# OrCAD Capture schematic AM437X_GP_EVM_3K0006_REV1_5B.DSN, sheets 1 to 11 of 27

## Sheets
1 Pg26: USB JTAG: size C; title: AM4378 General Purpose EVM; rev: 1.5B; company: Texas Instruments; note: am437x_gp_evm_3k0006_rev1_5b.dsn; note: ARM MPU BU; note: Final
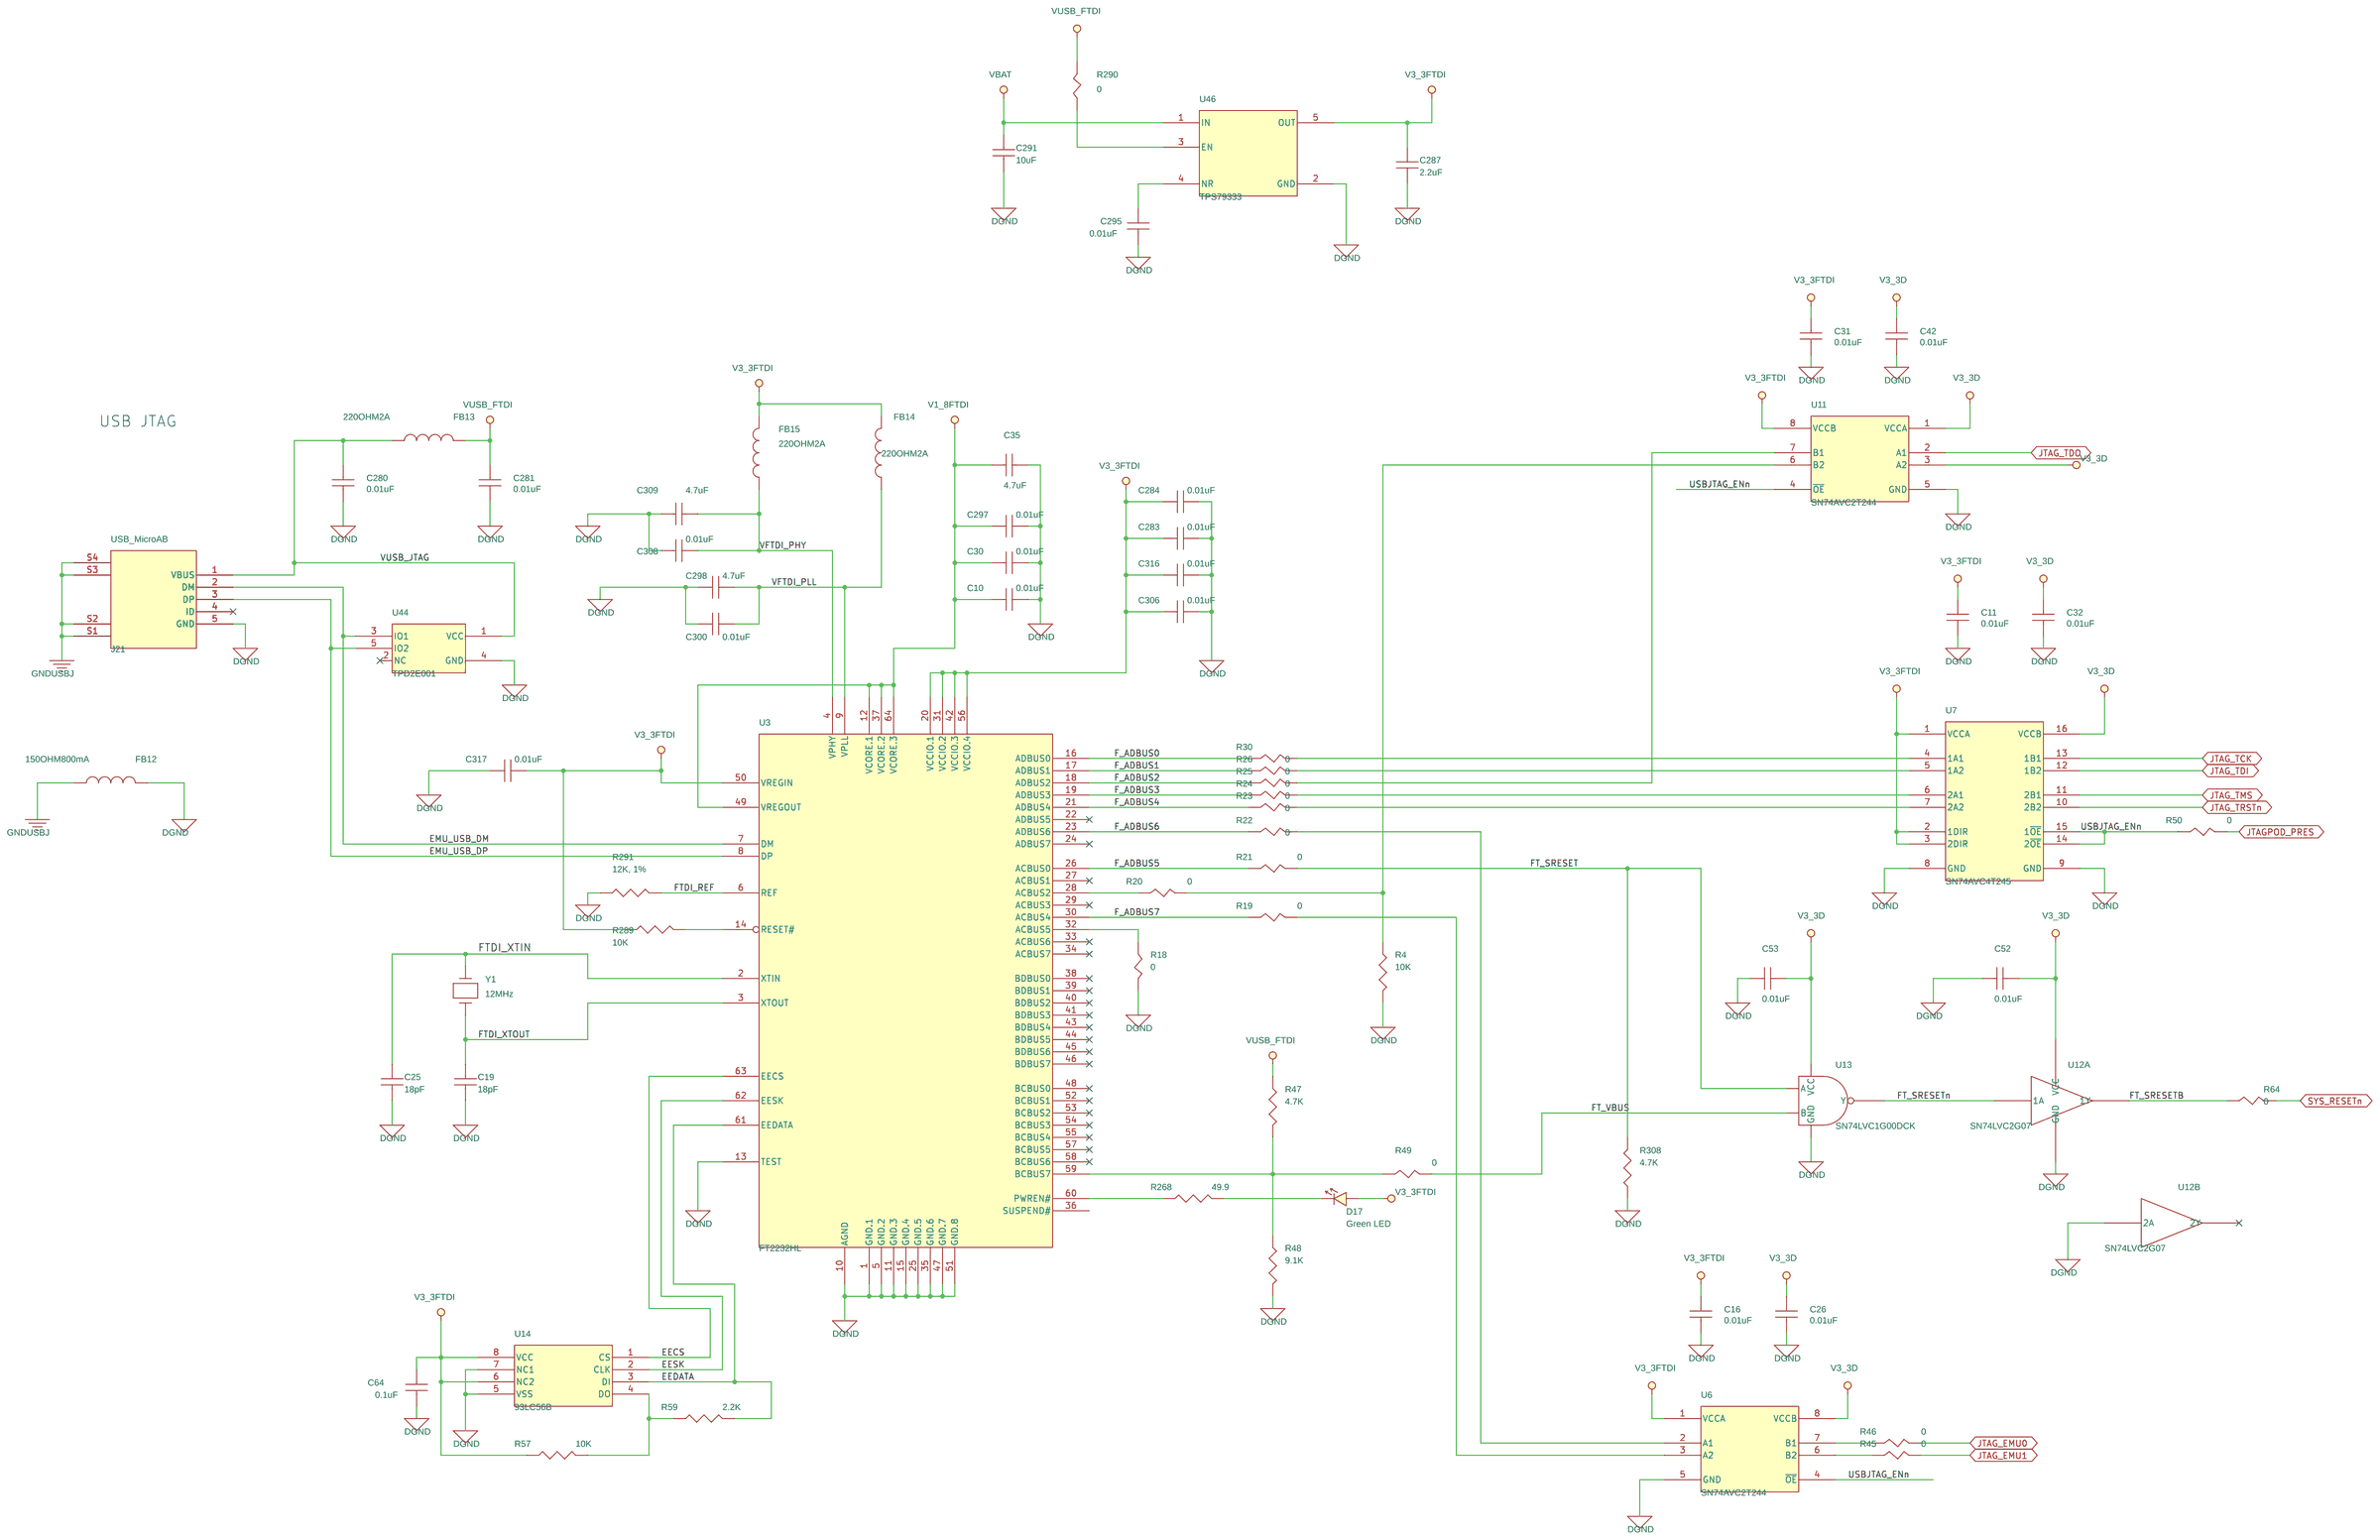
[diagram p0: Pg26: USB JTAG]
2 Pg11: Audio: size C
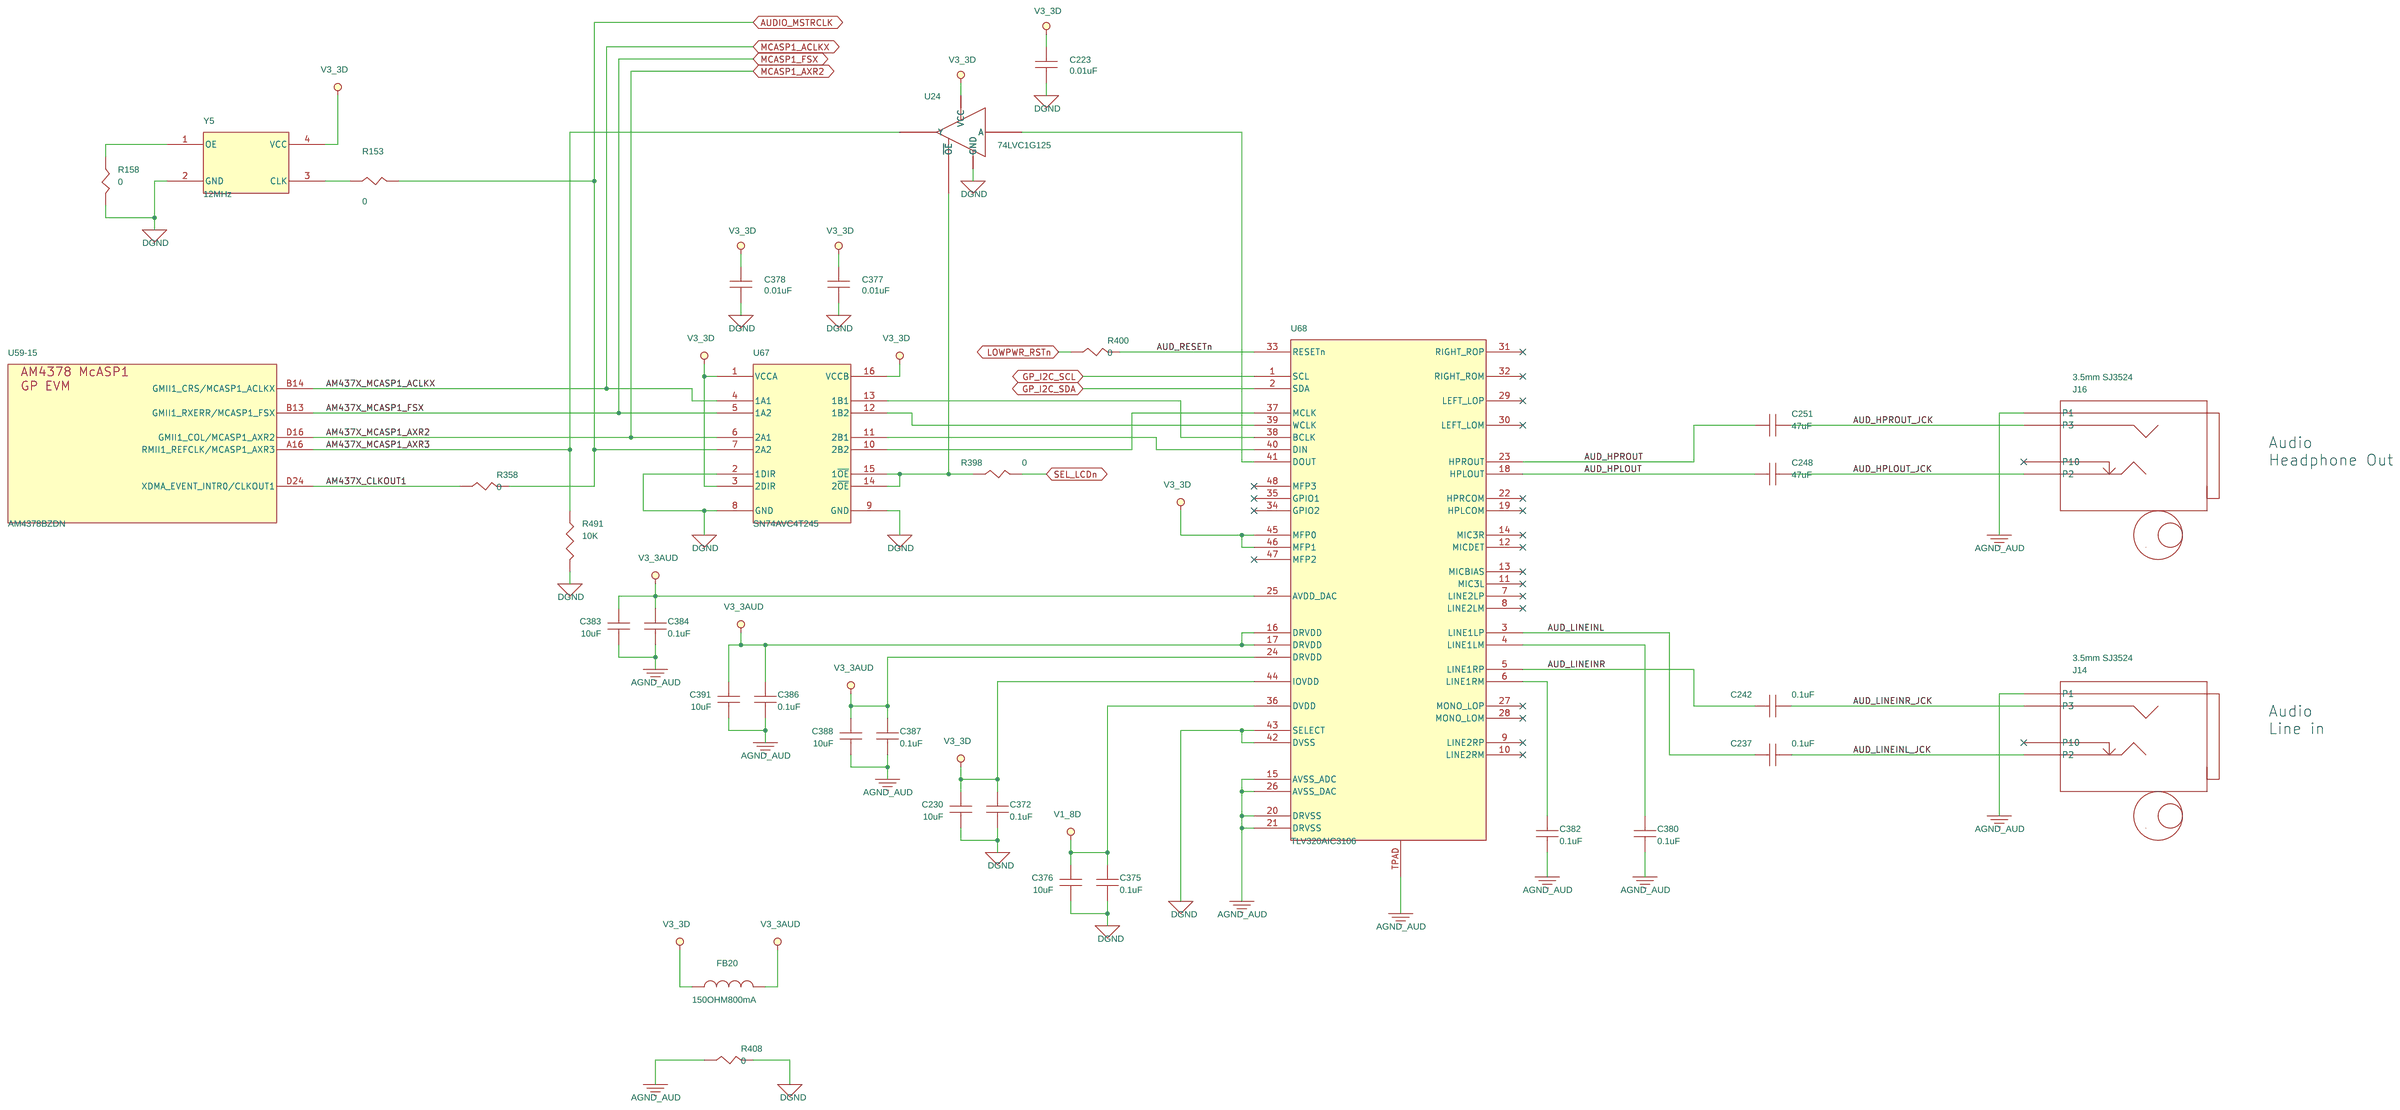
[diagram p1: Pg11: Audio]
3 Pg16: ADC: size C
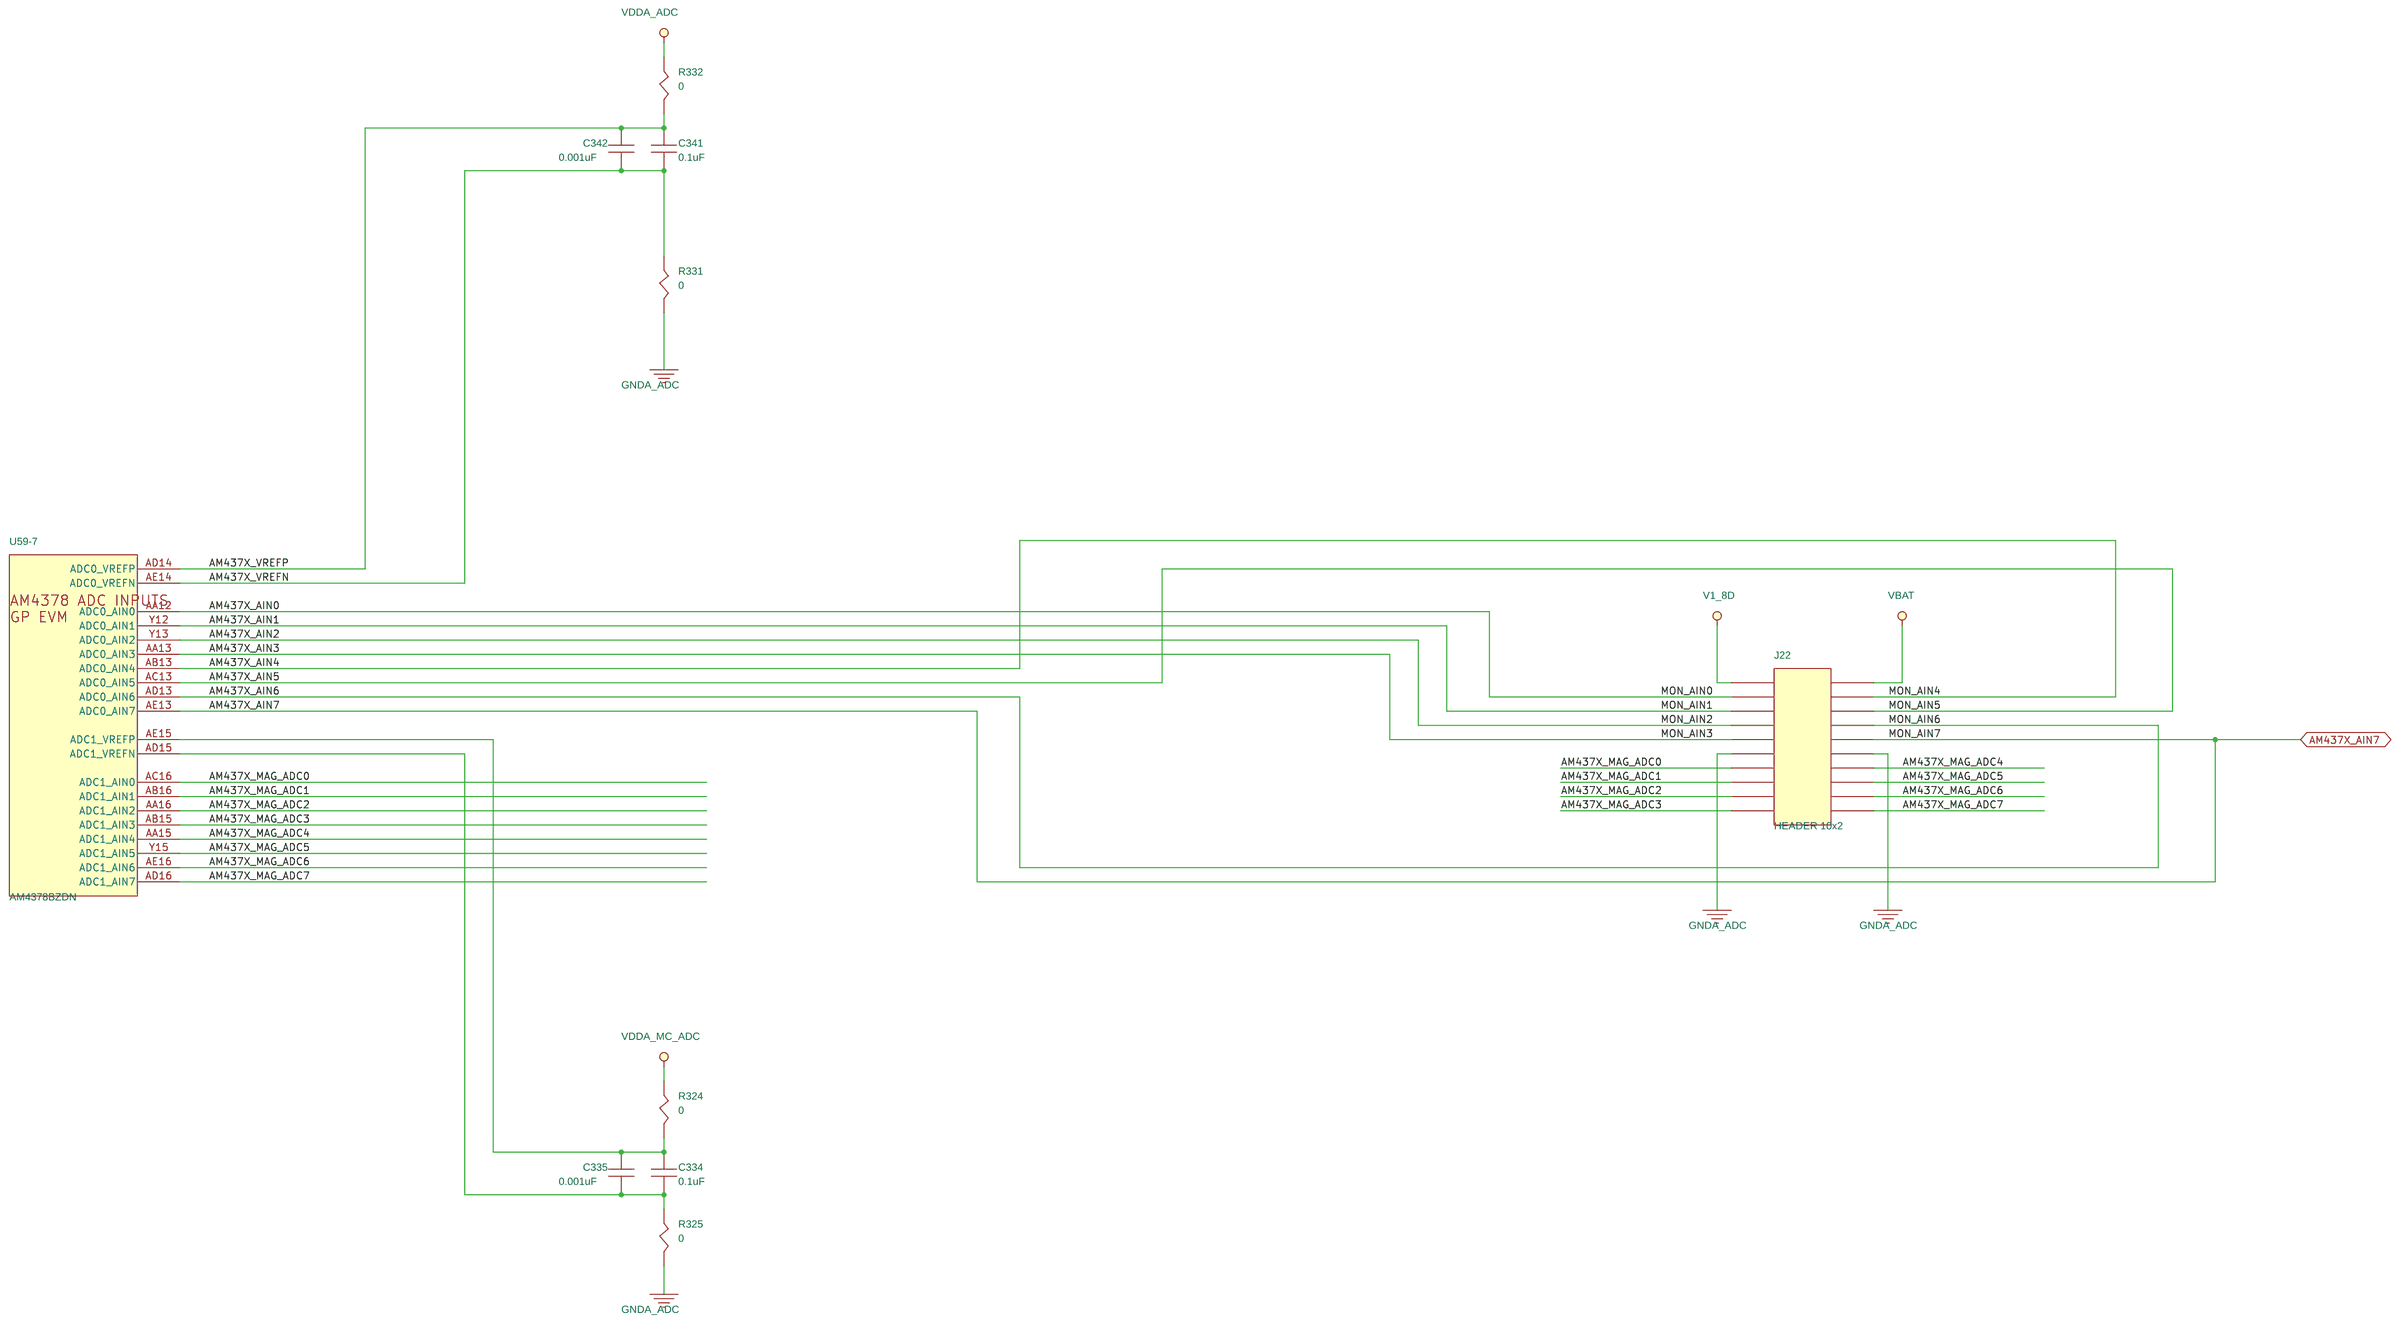
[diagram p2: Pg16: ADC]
4 Pg12: LCD: size C
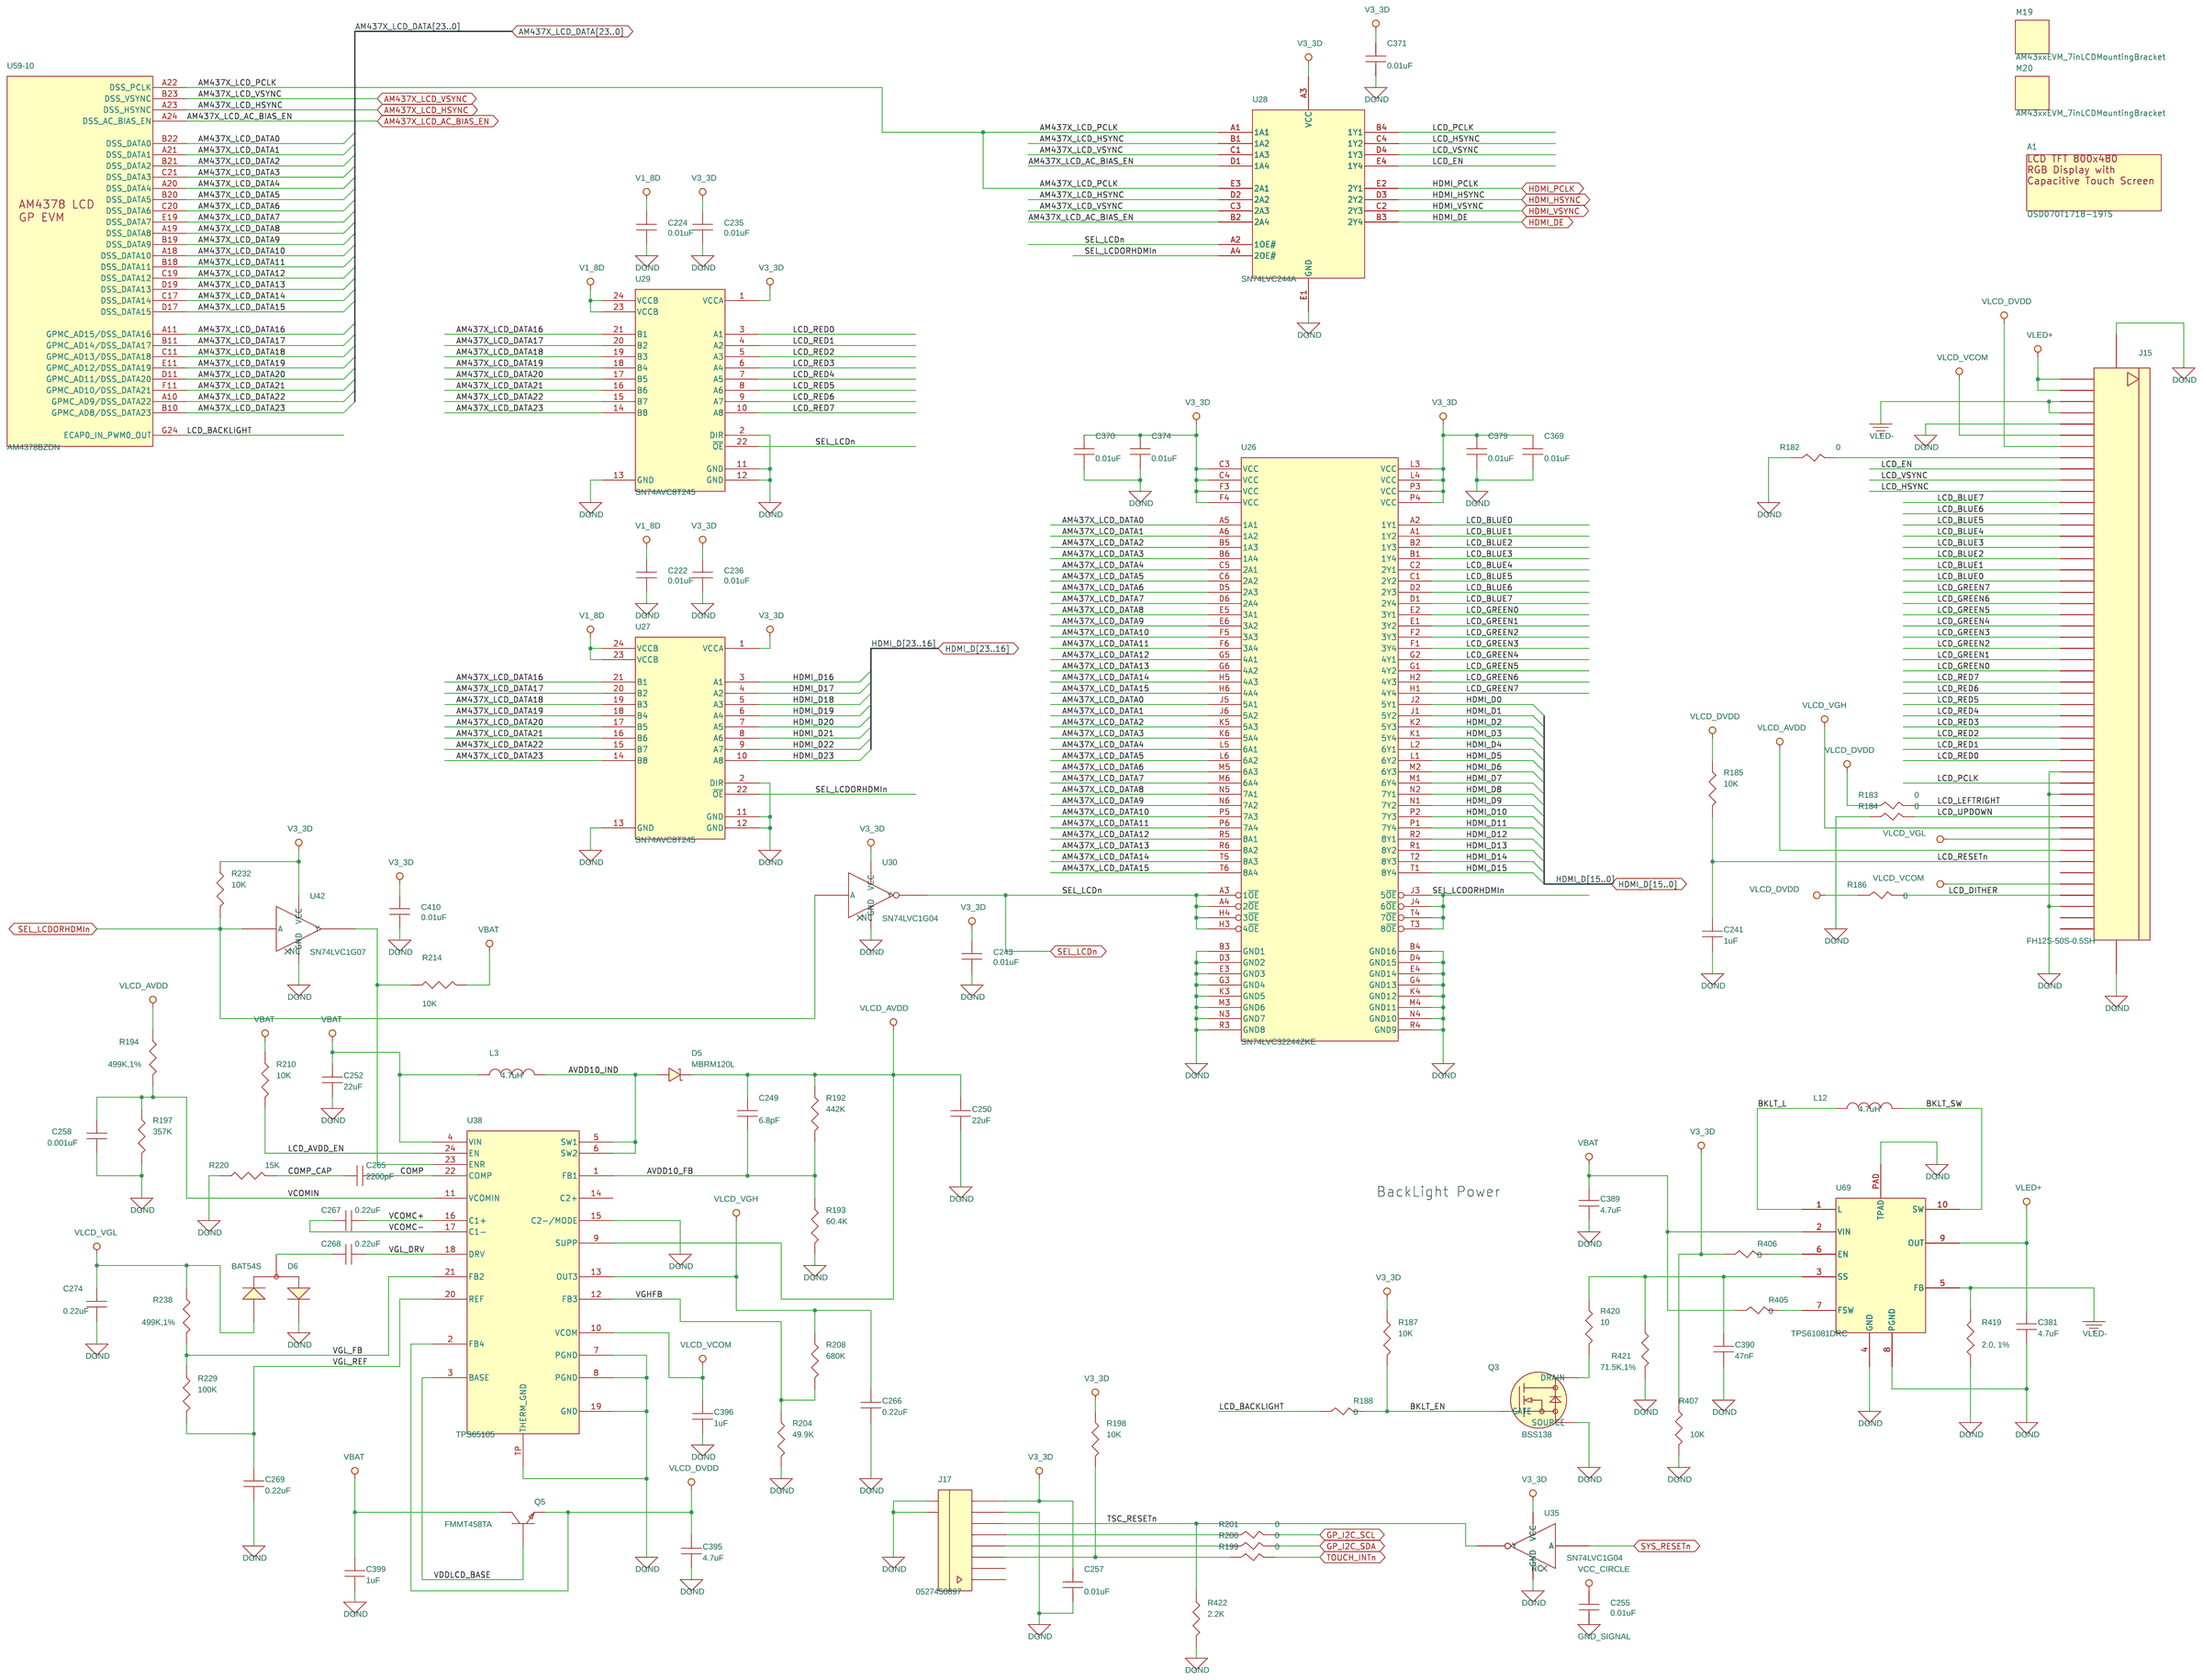
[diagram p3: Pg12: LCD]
5 Pg13: HDMI: size C
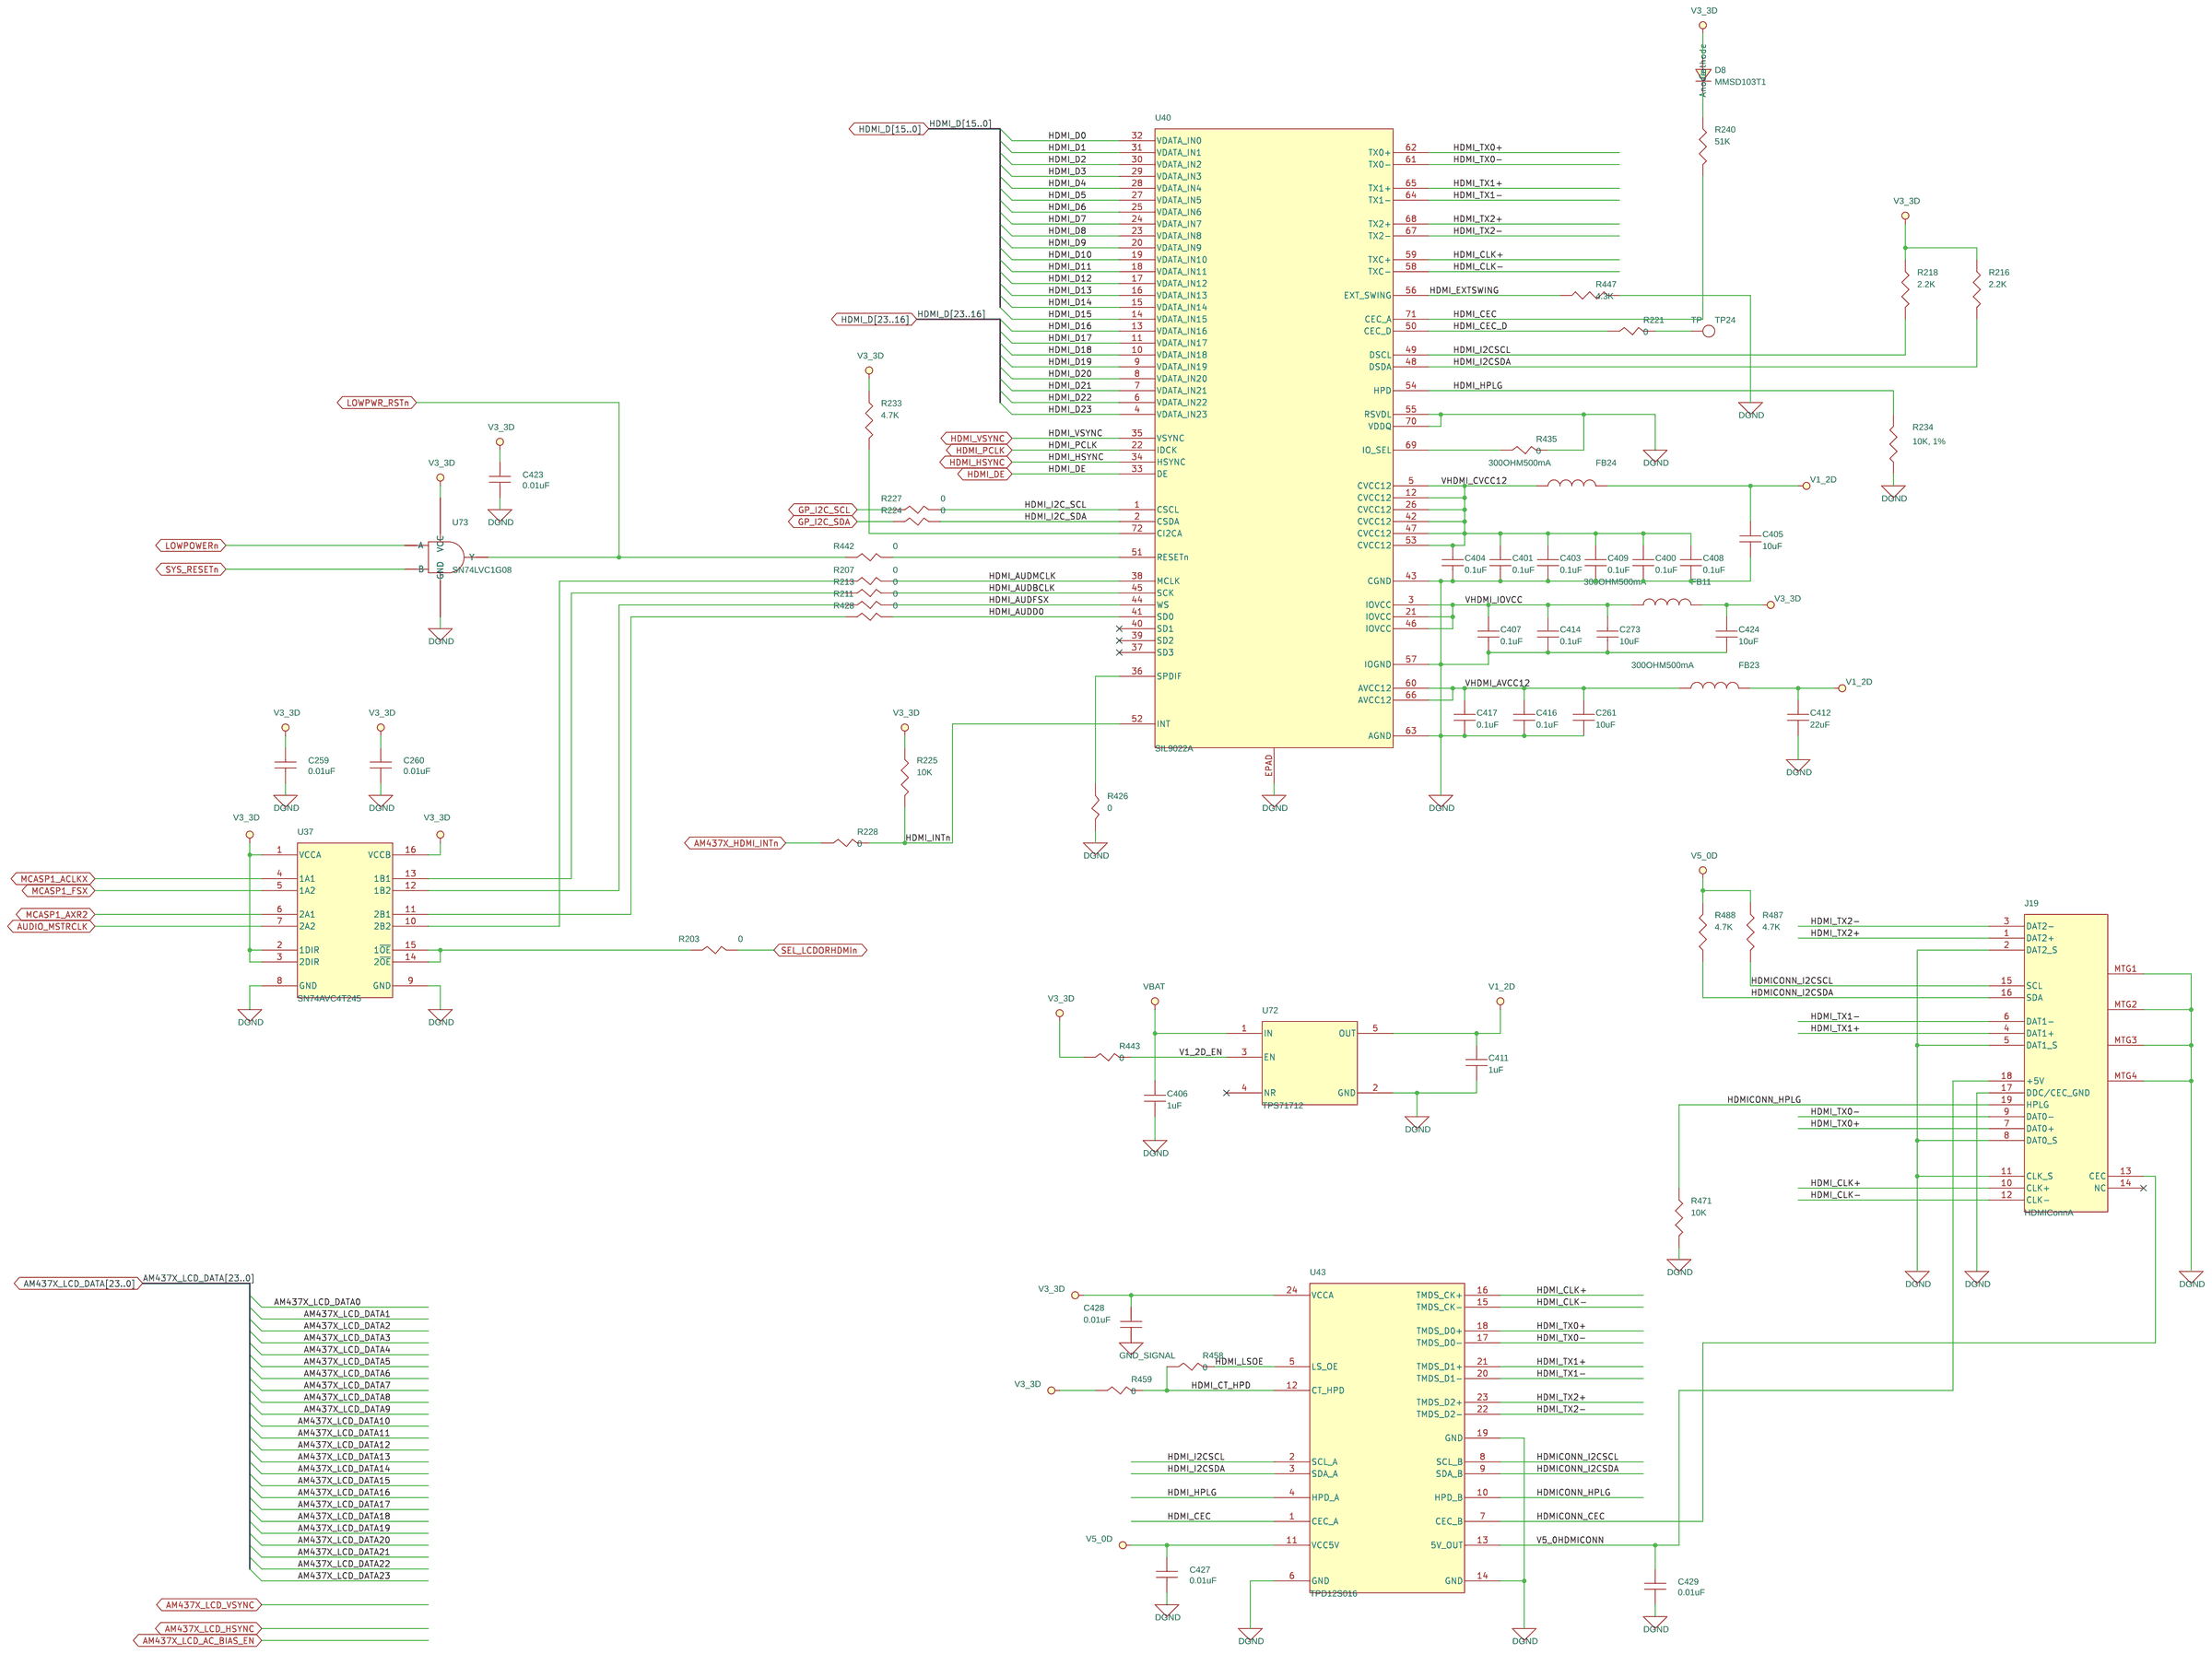
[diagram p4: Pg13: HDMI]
6 Pg21: CAN #0: size C
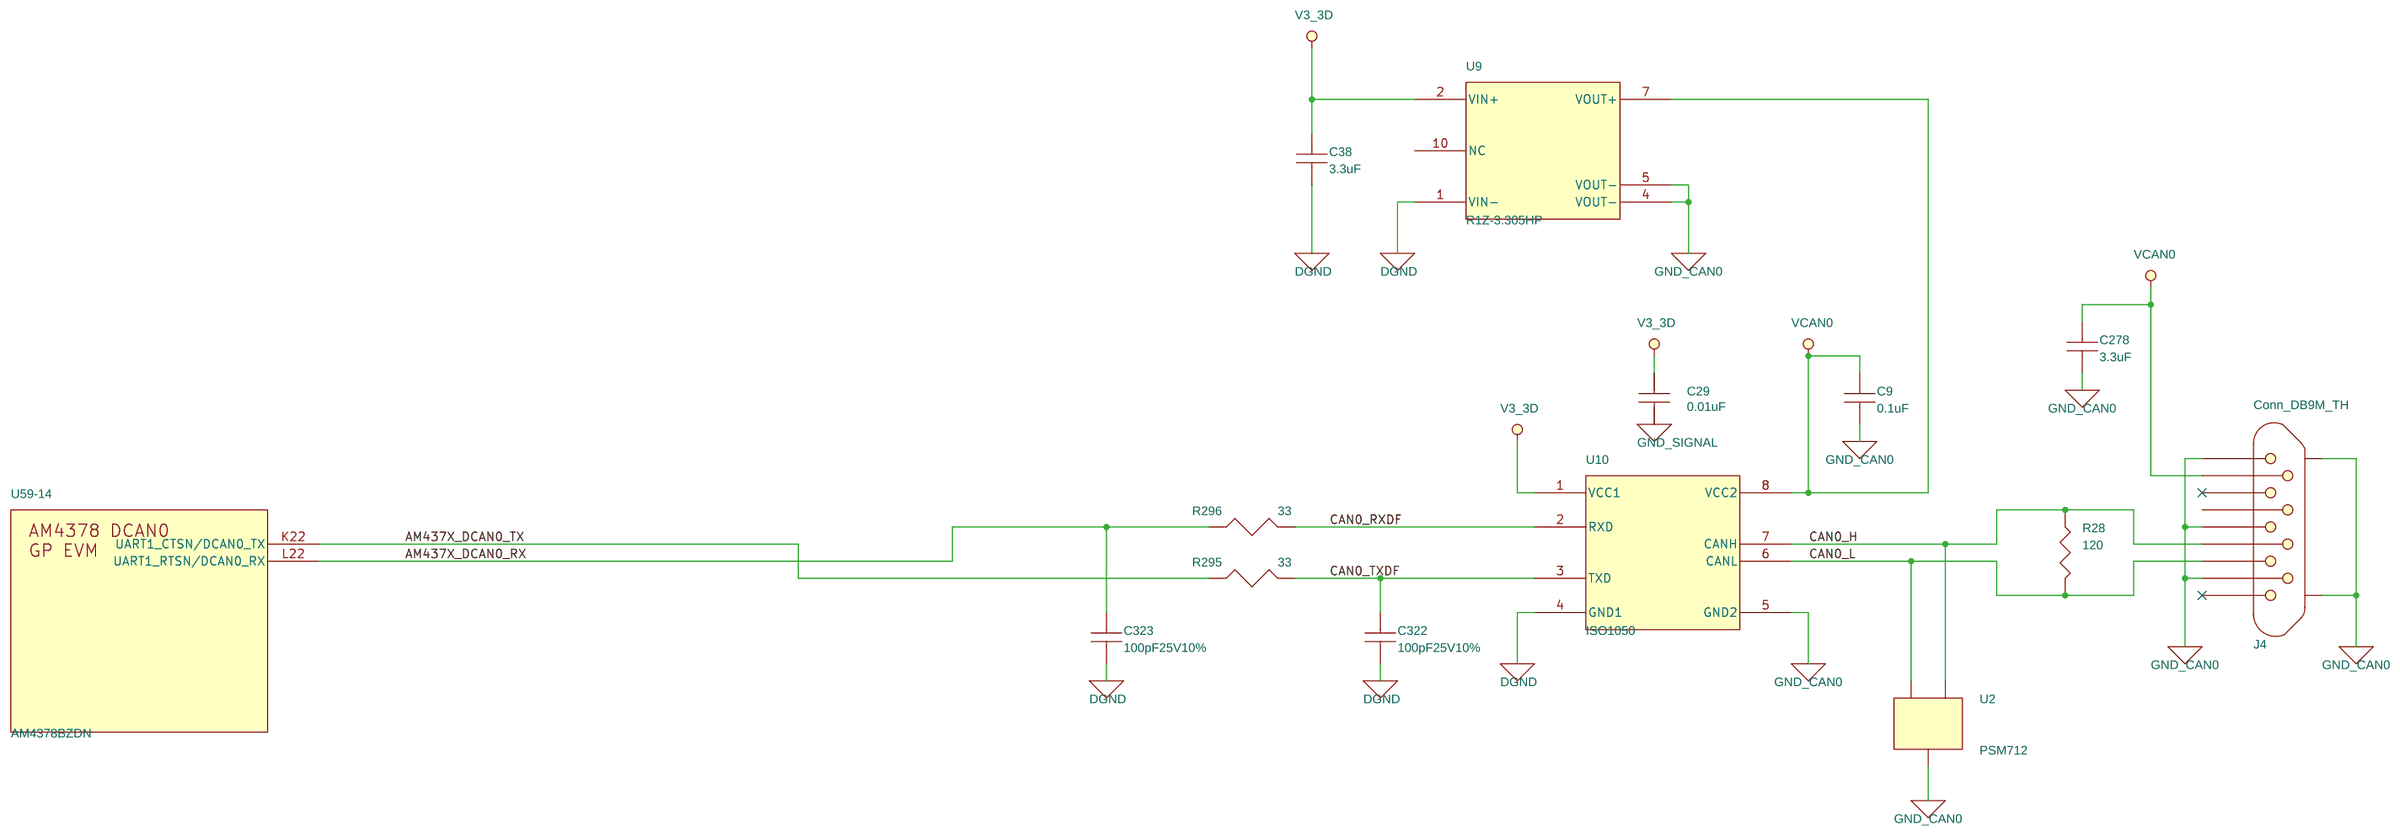
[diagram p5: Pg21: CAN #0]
7 Pg09: UART#0: size C
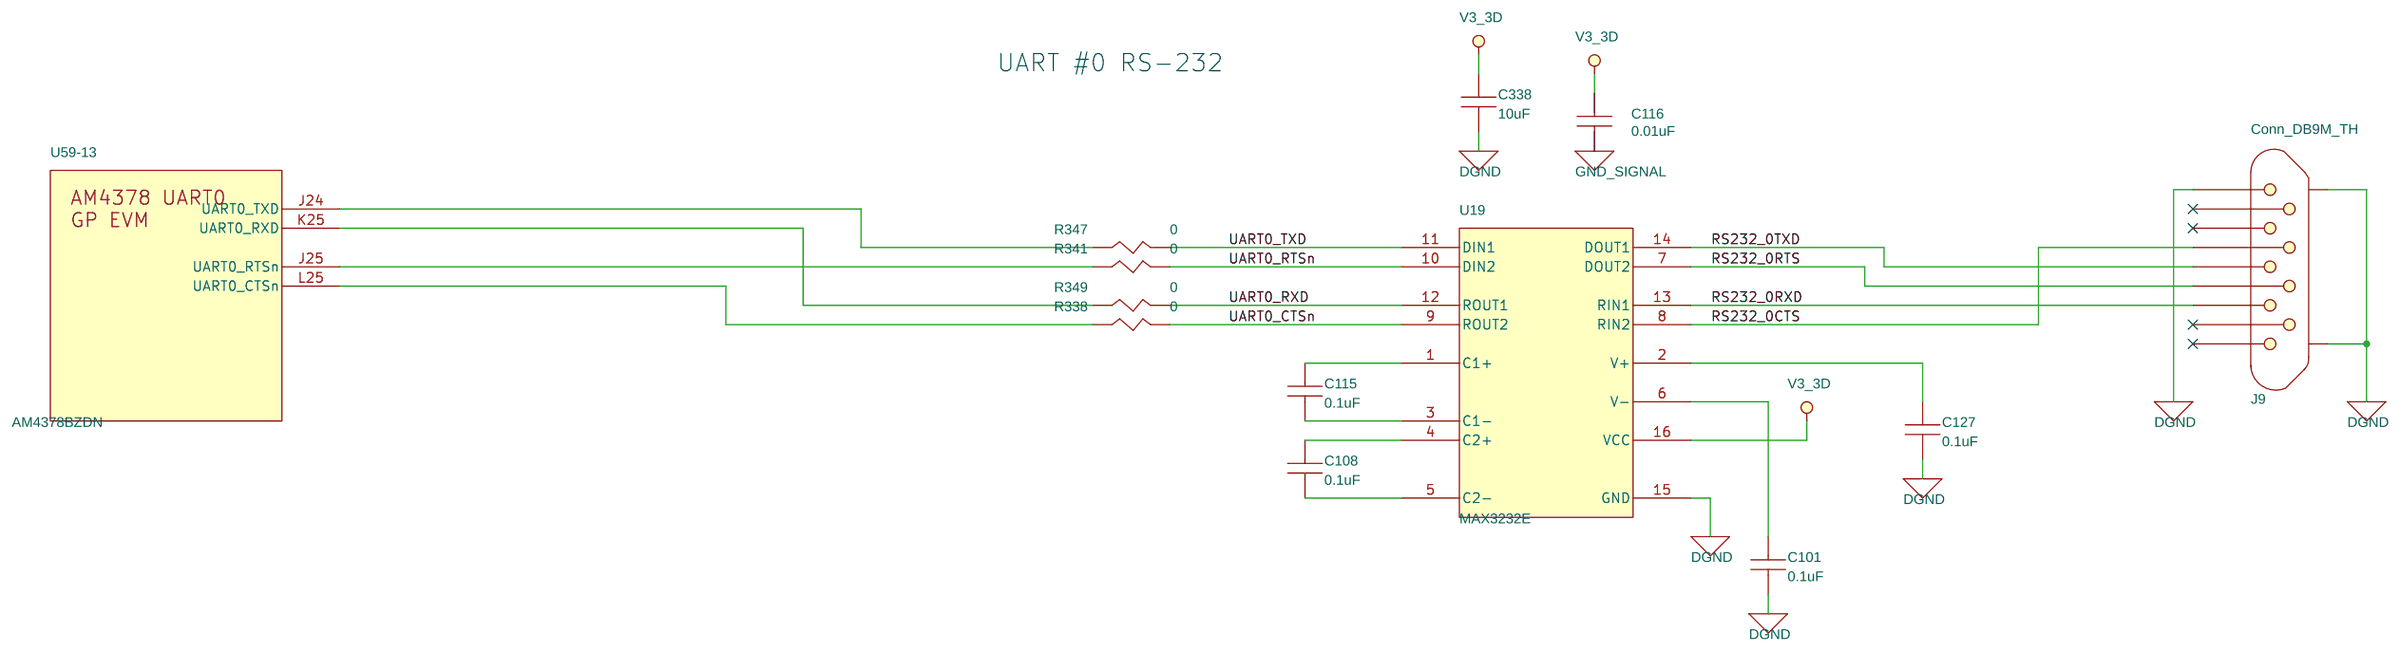
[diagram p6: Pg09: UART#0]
8 Pg22: CAN #1: size C
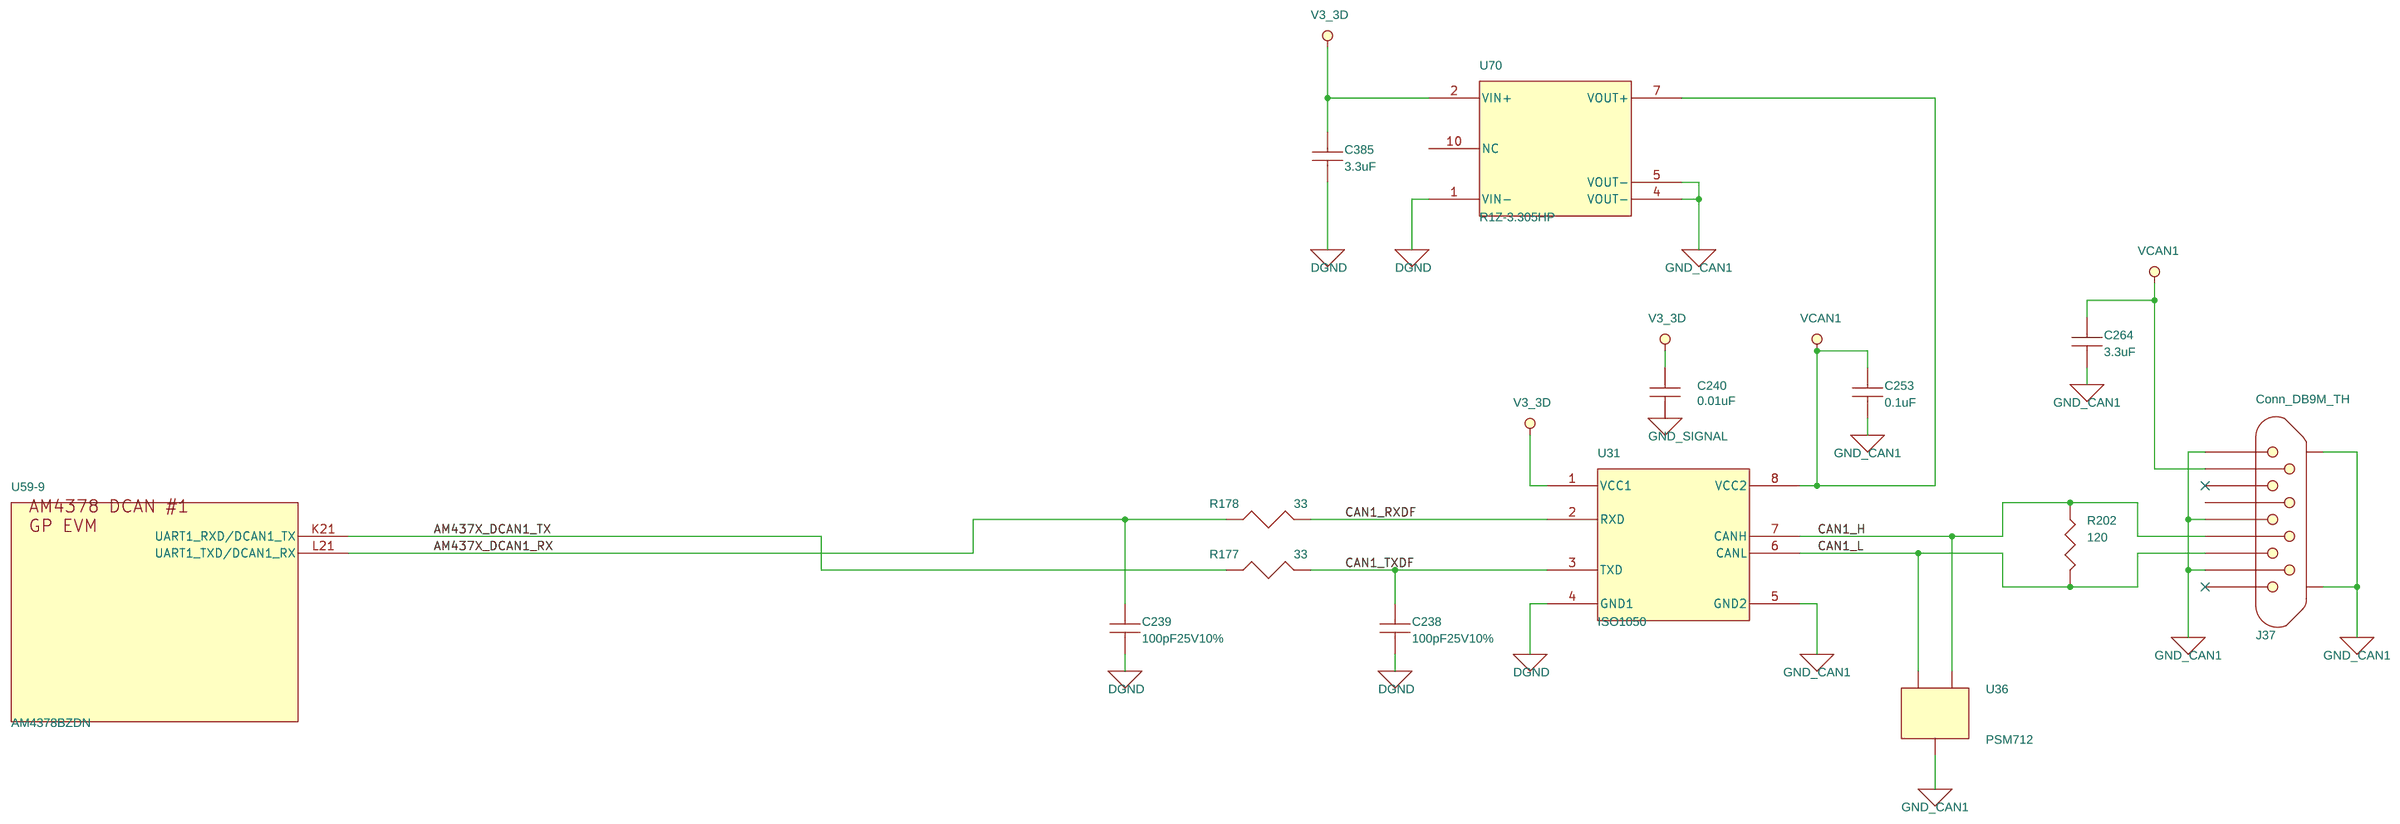
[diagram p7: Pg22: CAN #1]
9 Pg18: USB Port #1: size C
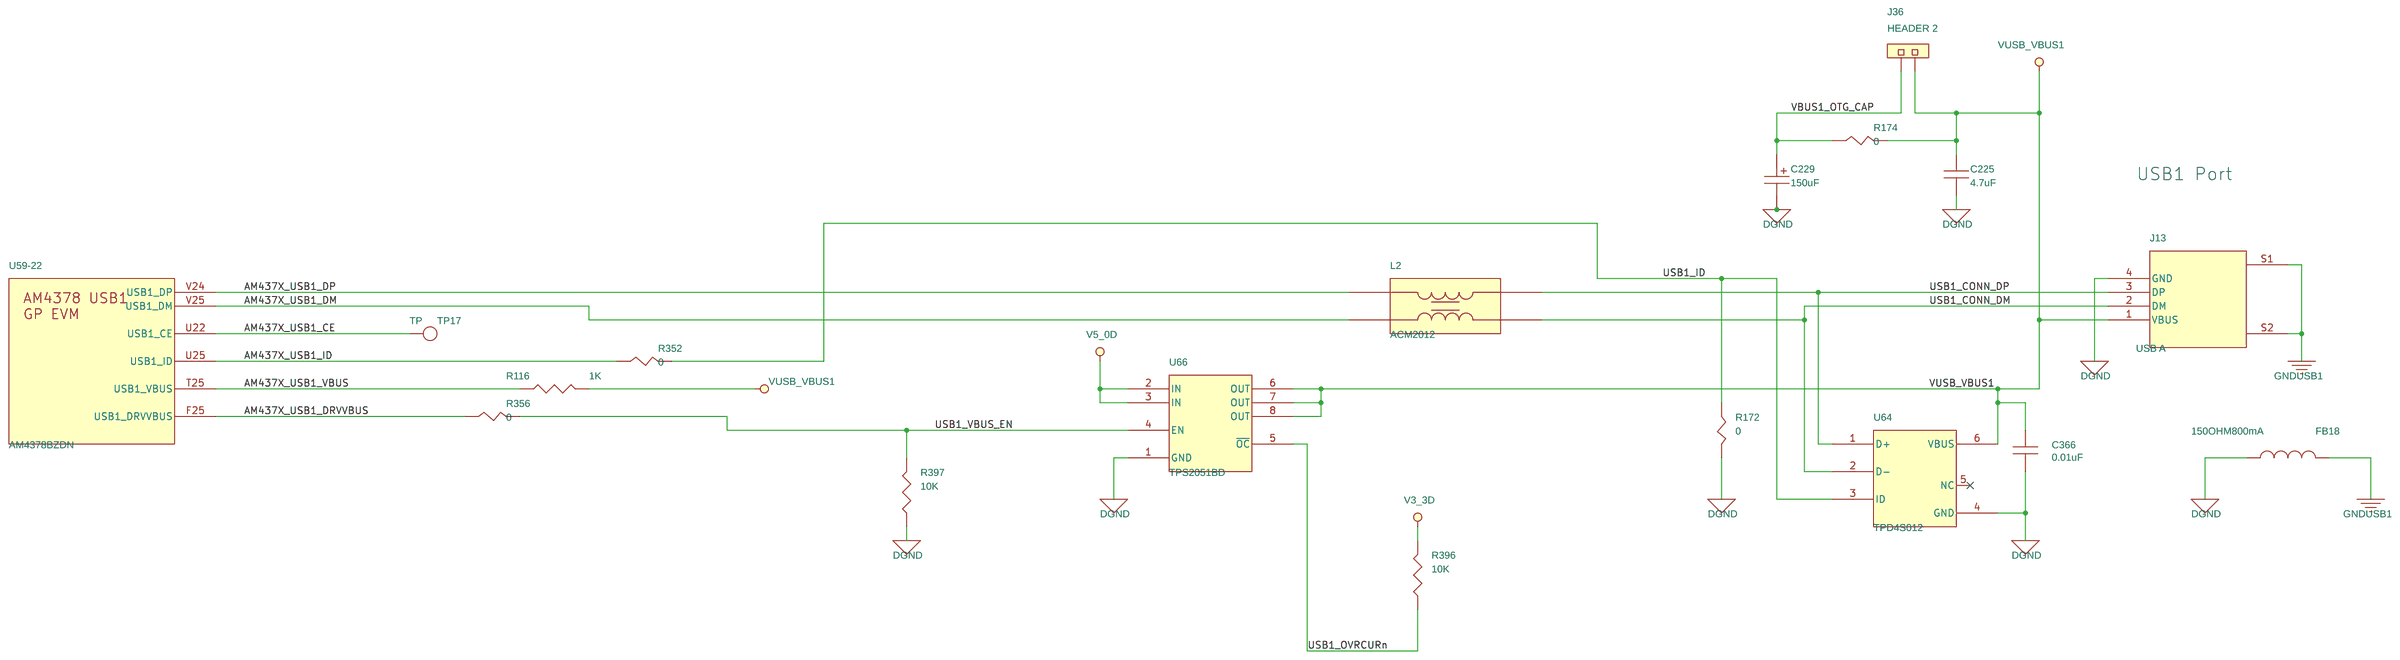
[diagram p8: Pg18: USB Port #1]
10 Pg25: JTAG Debug: size C
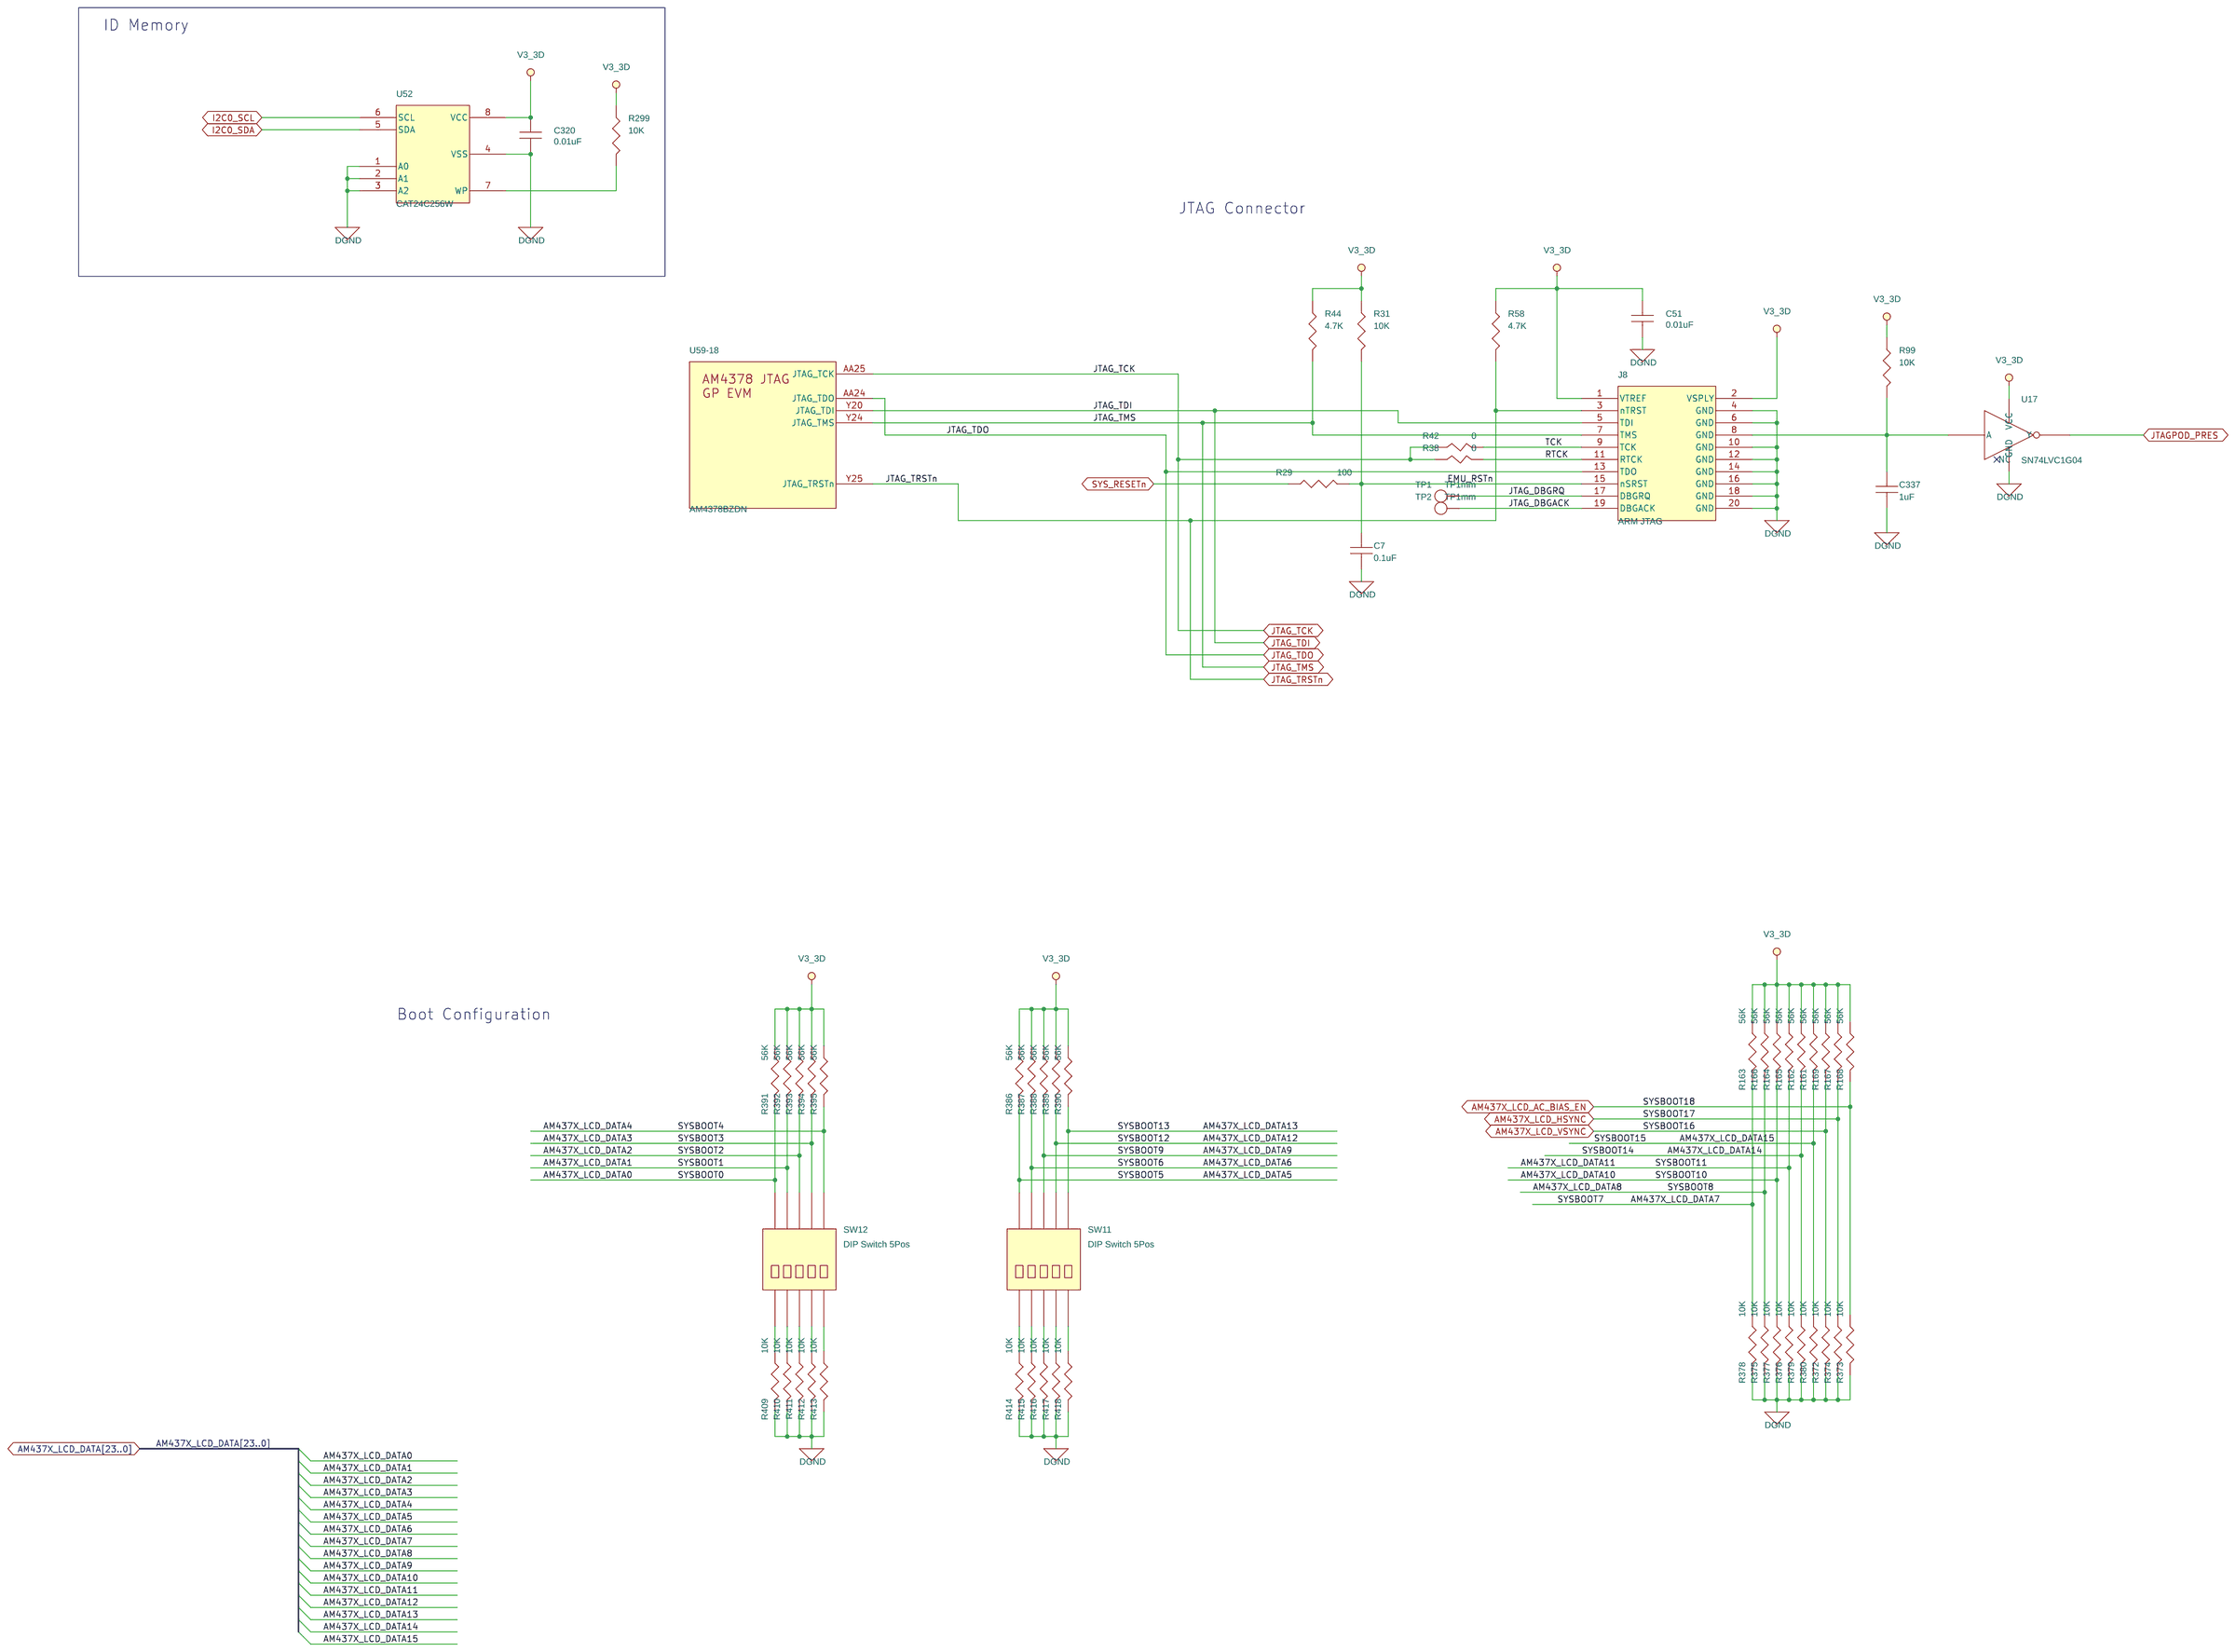
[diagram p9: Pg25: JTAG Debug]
11 Pg15: Camera #1: size C
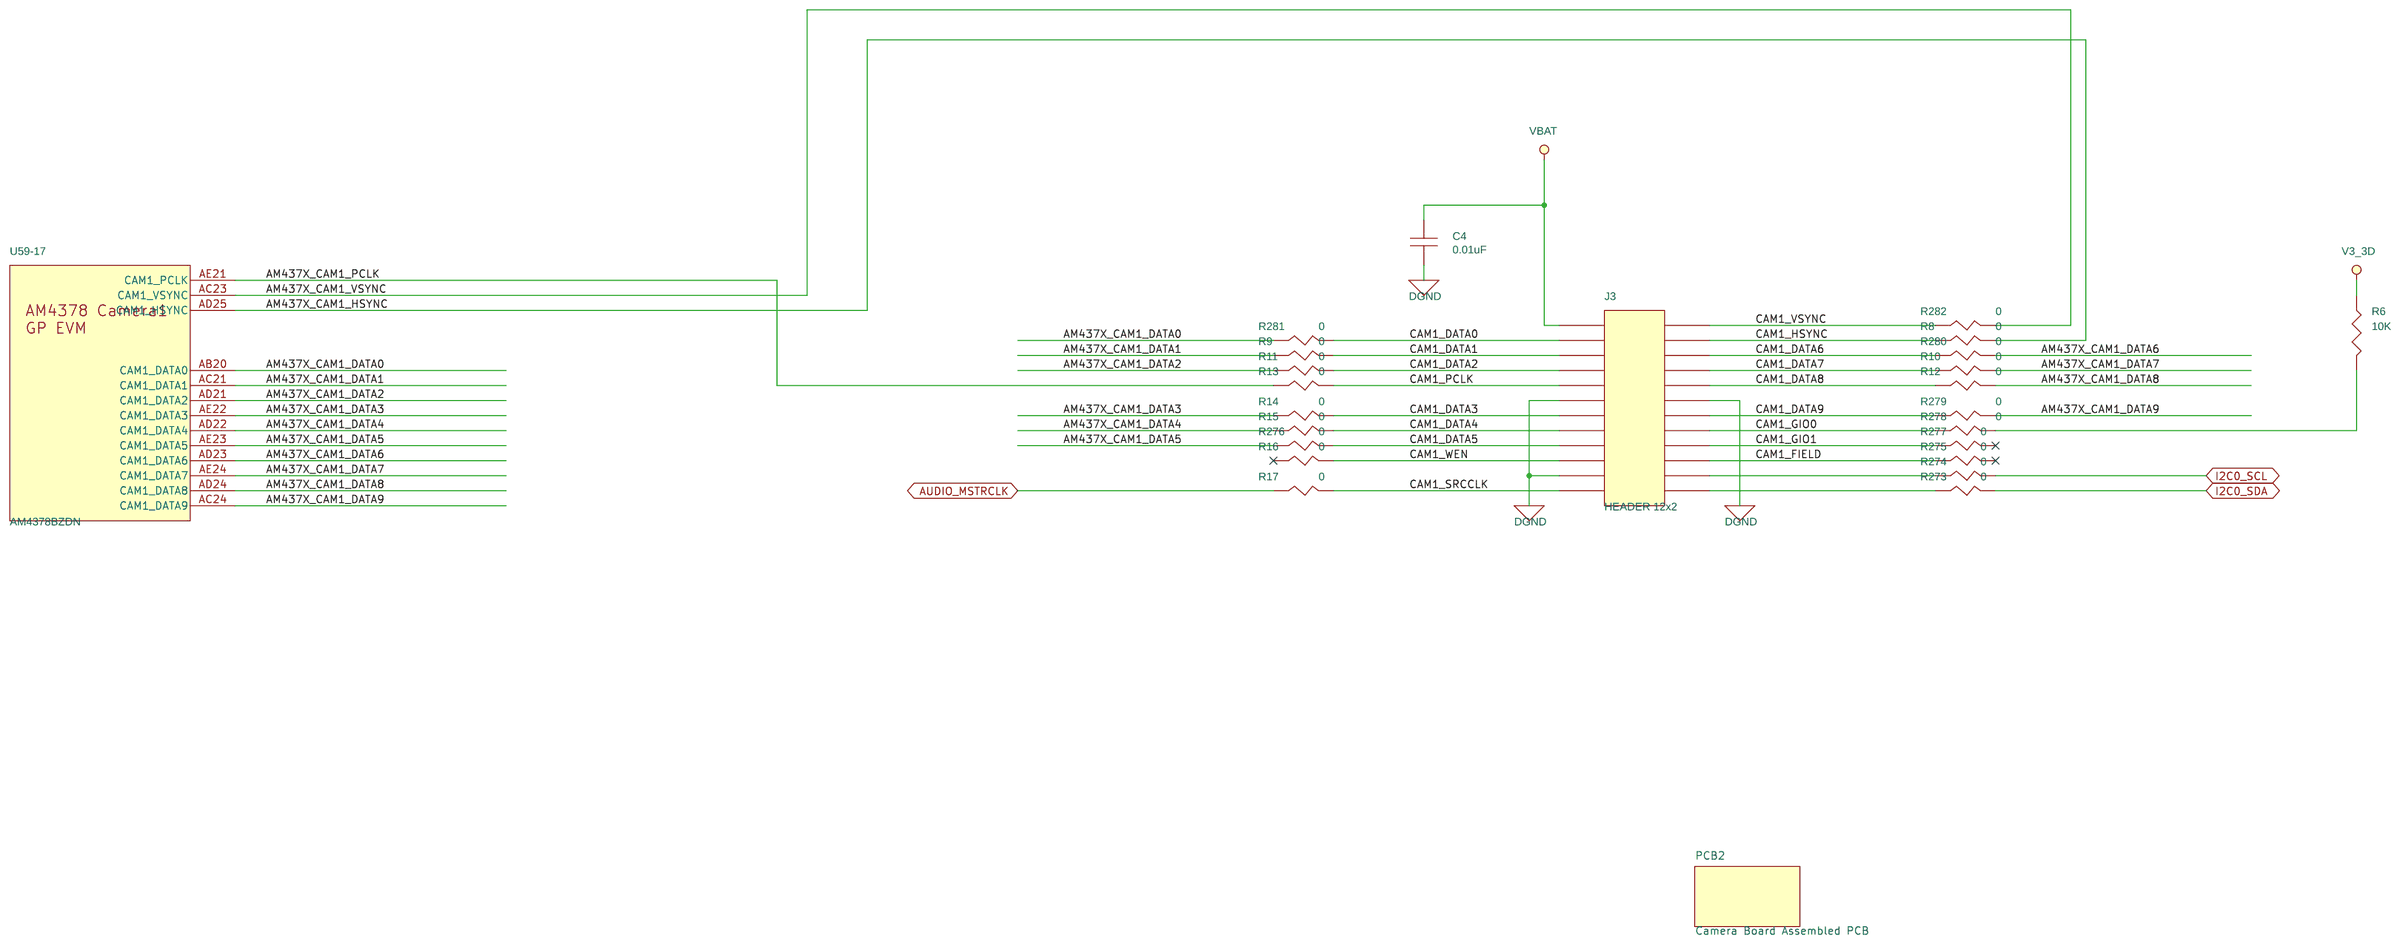
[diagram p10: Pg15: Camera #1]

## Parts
sheet Pg08: SDMMC0 Interface
U59  AM4378BZDN  [AM437X_ZDN]  (sections -1,-10,-11,-12,-13,-14,-15,-16,-17,-18,-19,-2,-20,-21,-22,-23,-24,-25,-3,-4,-5,-6,-7,-8,-9)
sheet Pg09: UART#0
C101  0.1uF  [SM-7351-CAP-0402]
C108  0.1uF  [SM-7351-CAP-0402]
C115  0.1uF  [SM-7351-CAP-0402]
C116  0.01uF  [SM-7351-CAP-0402]
C127  0.1uF  [SM-7351-CAP-0402]
C338  10uF  [SM-7351-CAP-0805]
J9  Conn_DB9M_TH  [norcomp_db9m_th]
R338  0  [SM-7351-RES-0402]
R341  0  [SM-7351-RES-0402]
R347  0  [SM-7351-RES-0402]
R349  0  [SM-7351-RES-0402]
U19  MAX3232E  [U_16_D]
sheet Pg11: Audio
C223  0.01uF  [SM-7351-CAP-0402]
C230  10uF  [SM-7351-CAP-0805]
C237  0.1uF  [SM-7351-CAP-0402]
C242  0.1uF  [SM-7351-CAP-0402]
C248  47uF  [SM-7351-CAP-1206]
C251  47uF  [SM-7351-CAP-1206]
C372  0.1uF  [SM-7351-CAP-0402]
C375  0.1uF  [SM-7351-CAP-0402]
C376  10uF  [SM-7351-CAP-0805]
C377  0.01uF  [SM-7351-CAP-0402]
C378  0.01uF  [SM-7351-CAP-0402]
C380  0.1uF  [SM-7351-CAP-0402]
C382  0.1uF  [SM-7351-CAP-0402]
C383  10uF  [SM-7351-CAP-0805]
C384  0.1uF  [SM-7351-CAP-0402]
C386  0.1uF  [SM-7351-CAP-0402]
C387  0.1uF  [SM-7351-CAP-0402]
C388  10uF  [SM-7351-CAP-0805]
C391  10uF  [SM-7351-CAP-0805]
FB20  150OHM800mA  [sm-7351-ind-0805]
J14  3.5mm SJ3524  [sj3524smt4pin]
J16  3.5mm SJ3524  [sj3524smt4pin]
R153  0  [SM-7351-RES-0402]
R158  0  [SM-7351-RES-0402]
R358  0  [SM-7351-RES-0402]
R398  0  [SM-7351-RES-0402]
R400  0  [SM-7351-RES-0402]
R408  0  [SM-7351-RES-0603]
R491  10K  [SM-7351-RES-0402]
U24  74LVC1G125  [SC70-5-43M]
U67  SN74AVC4T245  [U_16_PW]
U68  TLV320AIC3106  [vqfn48_rgz]
Y5  12MHz  [ecs_smd3_2x5mm]
sheet Pg12: LCD
A1  OSD070T1718-19TS  [DNP]
C222  0.01uF  [SM-7351-CAP-0402]
C224  0.01uF  [SM-7351-CAP-0402]
C235  0.01uF  [SM-7351-CAP-0402]
C236  0.01uF  [SM-7351-CAP-0402]
C241  1uF  [SM-7351-CAP-0402]
C243  0.01uF  [SM-7351-CAP-0402]
C249  6.8pF  [SM-7351-CAP-0402]
C250  22uF  [SM-7351-CAP-0805]
C252  22uF  [SM-7351-CAP-0805]
C255  0.01uF  [SM-7351-CAP-0402]
C257  0.01uF  [SM-7351-CAP-0402]
C258  0.001uF  [SM-7351-CAP-0402]
C265  2200pF  [SM-7351-CAP-0402]
C266  0.22uF  [SM-7351-CAP-0603]
C267  0.22uF  [SM-7351-CAP-0603]
C268  0.22uF  [SM-7351-CAP-0603]
C269  0.22uF  [SM-7351-CAP-0603]
C274  0.22uF  [SM-7351-CAP-0603]
C369  0.01uF  [SM-7351-CAP-0402]
C370  0.01uF  [SM-7351-CAP-0402]
C371  0.01uF  [SM-7351-CAP-0402]
C374  0.01uF  [SM-7351-CAP-0402]
C379  0.01uF  [SM-7351-CAP-0402]
C381  4.7uF  [SM-7351-CAP-0805]
C389  4.7uF  [SM-7351-CAP-0603]
C390  47nF  [SM-7351-CAP-0402]
C395  4.7uF  [SM-7351-CAP-0603]
C396  1uF  [SM-7351-CAP-0402]
C399  1uF  [SM-7351-CAP-0402]
C410  0.01uF  [SM-7351-CAP-0402]
D5  MBRM120L  [SM_DIO_CASE_457-04]
D6  BAT54S  [SM_SOT323-3]
J15  FH12S-50S-0.5SH  [cnfh12s-50s-05sh]
J17  0527450897  [CN527450-897]
L3  4.7uH  [sm_ind_lqh32cn]
L12  4.7uH  [vlcf5020t]
M19  AM43xxEVM_7inLCDMountingBracket  [DNP]
M20  AM43xxEVM_7inLCDMountingBracket  [DNP]
Q3  BSS138  [SOT23-3]
Q5  FMMT458TA  [sm_sot23_bce]
R182  0  [SM-7351-RES-0402]
R183  0  [SM-7351-RES-0402]
R184  0  [SM-7351-RES-0402]
R185  10K  [SM-7351-RES-0402]
R186  0  [SM-7351-RES-0402]
R187  10K  [SM-7351-RES-0402]
R188  0  [SM-7351-RES-0402]
R192  442K  [SM-7351-RES-0402]
R193  60.4K  [SM-7351-RES-0402]
R194  499K,1%  [SM-7351-RES-0402]
R197  357K  [SM-7351-RES-0402]
R198  10K  [SM-7351-RES-0402]
R199  0  [SM-7351-RES-0402]
R200  0  [SM-7351-RES-0402]
R201  0  [SM-7351-RES-0402]
R204  49.9K  [SM-7351-RES-0402]
R208  680K  [SM-7351-RES-0402]
R210  10K  [SM-7351-RES-0402]
R214  10K  [SM-7351-RES-0402]
R220  15K  [SM-7351-RES-0402]
R229  100K  [SM-7351-RES-0402]
R232  10K  [SM-7351-RES-0402]
R238  499K,1%  [SM-7351-RES-0402]
R405  0  [SM-7351-RES-0402]
R406  0  [SM-7351-RES-0402]
R407  10K  [SM-7351-RES-0402]
R419  2.0, 1%  [SM-7351-RES-0603]
R420  10  [SM-7351-RES-0402]
R421  71.5K,1%  [SM-7351-RES-0402]
R422  2.2K  [sm-7351-res-0402]
U26  SN74LVC32244ZKE  [bga13x5-96]
U27  SN74AVC8T245  [TSSOP8x4-24-47m]
U28  SN74LVC244A  [bga3x4-20-39m]
U29  SN74AVC8T245  [TSSOP8x4-24-47m]
U30  SN74LVC1G04  [SC70-5-43M]
U35  SN74LVC1G04  [SC70-5-43M]
U38  TPS65105  [u_24_pw]
U42  SN74LVC1G07  [SC70-5-43M]
U69  TPS61081DRC  [u_10_drc]
sheet Pg13: HDMI
C259  0.01uF  [SM-7351-CAP-0402]
C260  0.01uF  [SM-7351-CAP-0402]
C261  10uF  [SM-7351-CAP-0805]
C273  10uF  [SM-7351-CAP-0805]
C400  0.1uF  [SM-7351-CAP-0402]
C401  0.1uF  [SM-7351-CAP-0402]
C403  0.1uF  [SM-7351-CAP-0402]
C404  0.1uF  [SM-7351-CAP-0402]
C405  10uF  [SM-7351-CAP-0805]
C406  1uF  [SM-7351-CAP-0402]
C407  0.1uF  [SM-7351-CAP-0402]
C408  0.1uF  [SM-7351-CAP-0402]
C409  0.1uF  [SM-7351-CAP-0402]
C411  1uF  [SM-7351-CAP-0402]
C412  22uF  [SM-7351-CAP-0805]
C414  0.1uF  [SM-7351-CAP-0402]
C416  0.1uF  [SM-7351-CAP-0402]
C417  0.1uF  [SM-7351-CAP-0402]
C423  0.01uF  [SM-7351-CAP-0402]
C424  10uF  [SM-7351-CAP-0805]
C427  0.01uF  [SM-7351-CAP-0402]
C428  0.01uF  [SM-7351-CAP-0402]
C429  0.01uF  [SM-7351-CAP-0402]
D8  MMSD103T1  [sod-123]
FB11  300OHM500mA  [sm-7351-ind-0603]
FB23  300OHM500mA  [sm-7351-ind-0603]
FB24  300OHM500mA  [sm-7351-ind-0603]
J19  HDMIConnA  [smd_hdmia_ra]
R203  0  [SM-7351-RES-0402]
R207  0  [SM-7351-RES-0402]
R211  0  [SM-7351-RES-0402]
R213  0  [SM-7351-RES-0402]
R216  2.2K  [sm-7351-res-0402]
R218  2.2K  [sm-7351-res-0402]
R221  0  [SM-7351-RES-0402]
R224  0  [SM-7351-RES-0402]
R225  10K  [SM-7351-RES-0402]
R227  0  [SM-7351-RES-0402]
R228  0  [SM-7351-RES-0402]
R233  4.7K  [SM-7351-RES-0402]
R234  10K, 1%  [SM-7351-RES-0402]
R240  51K  [SM-7351-RES-0402]
R426  0  [SM-7351-RES-0402]
R428  0  [SM-7351-RES-0402]
R435  0  [SM-7351-RES-0402]
R442  0  [SM-7351-RES-0402]
R443  0  [SM-7351-RES-0402]
R447  4.3K  [SM-7351-RES-0402]
R458  0  [SM-7351-RES-0402]
R459  0  [SM-7351-RES-0402]
R471  10K  [SM-7351-RES-0402]
R487  4.7K  [SM-7351-RES-0402]
R488  4.7K  [SM-7351-RES-0402]
TP24  TP  [TH_TP_5002]
U37  SN74AVC4T245  [U_16_PW]
U40  SIL9022A  [QFN_72]
U43  TPD12S016  [pw_24pin_tssop]
U72  TPS71712  [smdsc70-5]
U73  SN74LVC1G08  [sm-so-sc70-5]
sheet Pg15: Camera #1
C4  0.01uF  [SM-7351-CAP-0402]
J3  HEADER 12x2  [hdr2x12]
PCB2  Camera Board Assembled PCB  [DNP]
R6  10K  [SM-7351-RES-0402]
R8  0  [SM-7351-RES-0402]
R9  0  [SM-7351-RES-0402]
R10  0  [SM-7351-RES-0402]
R11  0  [SM-7351-RES-0402]
R12  0  [SM-7351-RES-0402]
R13  0  [SM-7351-RES-0402]
R14  0  [SM-7351-RES-0402]
R15  0  [SM-7351-RES-0402]
R16  0  [SM-7351-RES-0402]
R17  0  [SM-7351-RES-0402]
R273  0  [SM-7351-RES-0402]
R274  0  [SM-7351-RES-0402]
R275  0  [SM-7351-RES-0402]
R276  0  [SM-7351-RES-0402]
R277  0  [SM-7351-RES-0402]
R278  0  [SM-7351-RES-0402]
R279  0  [SM-7351-RES-0402]
R280  0  [SM-7351-RES-0402]
R281  0  [SM-7351-RES-0402]
R282  0  [SM-7351-RES-0402]
sheet Pg16: ADC
C334  0.1uF  [SM-7351-CAP-0402]
C335  0.001uF  [SM-7351-CAP-0402]
C341  0.1uF  [SM-7351-CAP-0402]
C342  0.001uF  [SM-7351-CAP-0402]
J22  HEADER 10x2  [HDR2X10-330M]
R324  0  [SM-7351-RES-0402]
R325  0  [SM-7351-RES-0402]
R331  0  [SM-7351-RES-0402]
R332  0  [SM-7351-RES-0402]
sheet Pg18: USB Port #1
C225  4.7uF  [SM-7351-CAP-0603]
C229  150uF  [SM-7351-CAP-2917]
C366  0.01uF  [SM-7351-CAP-0402]
FB18  150OHM800mA  [sm-7351-ind-0805]
J13  USB A  [usb_std_a_th]
J36  HEADER 2  [header_2x1]
L2  ACM2012  [ACM2012H]
R116  1K  [SM-7351-RES-0402]
R172  0  [SM-7351-RES-0402]
R174  0  [SM-7351-RES-0603]
R352  0  [SM-7351-RES-0402]
R356  0  [SM-7351-RES-0402]
R396  10K  [SM-7351-RES-0402]
R397  10K  [SM-7351-RES-0402]
TP17  TP  [TH_TP_5002]
U64  TPD4S012  [U_6_DRY]
U66  TPS2051BD  [U_8_D]
sheet Pg21: CAN #0
C9  0.1uF  [SM-7351-CAP-0402]
C29  0.01uF  [SM-7351-CAP-0402]
C38  3.3uF  [SM-7351-CAP-0603]
C278  3.3uF  [SM-7351-CAP-0603]
C322  100pF25V10%  [SM-7351-CAP-0402]
C323  100pF25V10%  [SM-7351-CAP-0402]
J4  Conn_DB9M_TH  [norcomp_db9m_th]
R28  120  [SM-7351-RES-0402]
R295  33  [SM-7351-RES-0402]
R296  33  [SM-7351-RES-0402]
U2  PSM712  [sm-sot-23]
U9  R1Z-3.305HP  [smd15x11-6-374m]
U10  ISO1050  [so9x6-8-191m]
sheet Pg22: CAN #1
C238  100pF25V10%  [SM-7351-CAP-0402]
C239  100pF25V10%  [SM-7351-CAP-0402]
C240  0.01uF  [SM-7351-CAP-0402]
C253  0.1uF  [SM-7351-CAP-0402]
C264  3.3uF  [SM-7351-CAP-0603]
C385  3.3uF  [SM-7351-CAP-0603]
J37  Conn_DB9M_TH  [norcomp_db9m_th]
R177  33  [SM-7351-RES-0402]
R178  33  [SM-7351-RES-0402]
R202  120  [SM-7351-RES-0402]
U31  ISO1050  [so9x6-8-191m]
U36  PSM712  [sm-sot-23]
U70  R1Z-3.305HP  [smd15x11-6-374m]
sheet Pg25: JTAG Debug
C7  0.1uF  [SM-7351-CAP-0402]
C51  0.01uF  [SM-7351-CAP-0402]
C320  0.01uF  [SM-7351-CAP-0402]
C337  1uF  [SM-7351-CAP-0603]
J8  ARM JTAG  [hdr2x10-330m]
R29  100  [SM-7351-RES-0402]
R31  10K  [SM-7351-RES-0402]
R38  0  [SM-7351-RES-0402]
R42  0  [SM-7351-RES-0402]
R44  4.7K  [SM-7351-RES-0402]
R58  4.7K  [SM-7351-RES-0402]
R99  10K  [SM-7351-RES-0402]
R161  56K  [SM-7351-RES-0402]
R162  56K  [SM-7351-RES-0402]
R163  56K  [SM-7351-RES-0402]
R164  56K  [SM-7351-RES-0402]
R165  56K  [SM-7351-RES-0402]
R166  56K  [SM-7351-RES-0402]
R167  56K  [SM-7351-RES-0402]
R168  56K  [SM-7351-RES-0402]
R169  56K  [SM-7351-RES-0402]
R299  10K  [SM-7351-RES-0402]
R372  10K  [SM-7351-RES-0402]
R373  10K  [SM-7351-RES-0402]
R374  10K  [SM-7351-RES-0402]
R375  10K  [SM-7351-RES-0402]
R376  10K  [SM-7351-RES-0402]
R377  10K  [SM-7351-RES-0402]
R378  10K  [SM-7351-RES-0402]
R379  10K  [SM-7351-RES-0402]
R380  10K  [SM-7351-RES-0402]
R386  56K  [SM-7351-RES-0402]
R387  56K  [SM-7351-RES-0402]
R388  56K  [SM-7351-RES-0402]
R389  56K  [SM-7351-RES-0402]
R390  56K  [SM-7351-RES-0402]
R391  56K  [SM-7351-RES-0402]
R392  56K  [SM-7351-RES-0402]
R393  56K  [SM-7351-RES-0402]
R394  56K  [SM-7351-RES-0402]
R395  56K  [SM-7351-RES-0402]
R409  10K  [SM-7351-RES-0402]
R410  10K  [SM-7351-RES-0402]
R411  10K  [SM-7351-RES-0402]
R412  10K  [SM-7351-RES-0402]
R413  10K  [SM-7351-RES-0402]
R414  10K  [SM-7351-RES-0402]
R415  10K  [SM-7351-RES-0402]
R416  10K  [SM-7351-RES-0402]
R417  10K  [SM-7351-RES-0402]
R418  10K  [SM-7351-RES-0402]
SW11  DIP Switch 5Pos  [SW291-5M]
SW12  DIP Switch 5Pos  [SW291-5M]
TP1  TP1mm  [tp_smd1mmcircle]
TP2  TP1mm  [tp_smd1mmcircle]
U17  SN74LVC1G04  [SC70-5-43M]
U52  CAT24C256W  [SOIC_8]
sheet Pg26: USB JTAG
C10  0.01uF  [SM-7351-CAP-0402]
C11  0.01uF  [SM-7351-CAP-0402]
C16  0.01uF  [SM-7351-CAP-0402]
C19  18pF  [SM-7351-CAP-0402]
C25  18pF  [SM-7351-CAP-0402]
C26  0.01uF  [SM-7351-CAP-0402]
C30  0.01uF  [SM-7351-CAP-0402]
C31  0.01uF  [SM-7351-CAP-0402]
C32  0.01uF  [SM-7351-CAP-0402]
C35  4.7uF  [SM-7351-CAP-0603]
C42  0.01uF  [SM-7351-CAP-0402]
C52  0.01uF  [SM-7351-CAP-0402]
C53  0.01uF  [SM-7351-CAP-0402]
C64  0.1uF  [SM-7351-CAP-0402]
C280  0.01uF  [SM-7351-CAP-0402]
C281  0.01uF  [SM-7351-CAP-0402]
C283  0.01uF  [SM-7351-CAP-0402]
C284  0.01uF  [SM-7351-CAP-0402]
C287  2.2uF  [SM-7351-CAP-0805]
C291  10uF  [SM-7351-CAP-0805]
C295  0.01uF  [SM-7351-CAP-0402]
C297  0.01uF  [SM-7351-CAP-0402]
C298  4.7uF  [SM-7351-CAP-0603]
C300  0.01uF  [SM-7351-CAP-0402]
C306  0.01uF  [SM-7351-CAP-0402]
C308  0.01uF  [SM-7351-CAP-0402]
C309  4.7uF  [SM-7351-CAP-0603]
C316  0.01uF  [SM-7351-CAP-0402]
C317  0.01uF  [SM-7351-CAP-0402]
D17  Green LED  [sm_led_0805]
FB12  150OHM800mA  [sm-7351-ind-0805]
FB13  220OHM2A  [sm-7351-ind-0603]
FB14  220OHM2A  [sm-7351-ind-0603]
FB15  220OHM2A  [sm-7351-ind-0603]
J21  USB_MicroAB  [ZX62-AB-5PA]
R4  10K  [SM-7351-RES-0402]
R18  0  [SM-7351-RES-0402]
R19  0  [SM-7351-RES-0402]
R20  0  [SM-7351-RES-0402]
R21  0  [SM-7351-RES-0402]
R22  0  [SM-7351-RES-0402]
R23  0  [SM-7351-RES-0402]
R24  0  [SM-7351-RES-0402]
R25  0  [SM-7351-RES-0402]
R26  0  [SM-7351-RES-0402]
R30  0  [SM-7351-RES-0402]
R45  0  [SM-7351-RES-0402]
R46  0  [SM-7351-RES-0402]
R47  4.7K  [SM-7351-RES-0402]
R48  9.1K  [SM-7351-RES-0402]
R49  0  [SM-7351-RES-0402]
R50  0  [SM-7351-RES-0402]
R57  10K  [SM-7351-RES-0402]
R59  2.2K  [sm-7351-res-0402]
R64  0  [SM-7351-RES-0402]
R268  49.9  [SM-7351-RES-0402]
R289  10K  [SM-7351-RES-0402]
R290  0  [SM-7351-RES-0402]
R291  12K, 1%  [SM-7351-RES-0402]
R308  4.7K  [SM-7351-RES-0402]
U3  FT2232HL  [LQFP64pin]
U6  SN74AVC2T244  [son2x1-8-16m]
U7  SN74AVC4T245  [U_16_PW]
U11  SN74AVC2T244  [son2x1-8-16m]
U12  SN74LVC2G07  [U_6_DCK]  (sections A,B)
U13  SN74LVC1G00DCK  [SC70-5-43M]
U14  93LC56B  [SOIC8_MC]
U44  TPD2E001  [U_5_DRL]
U46  TPS79333  [U_5_DBV]
Y1  12MHz  [SM_OSC_ABM3]

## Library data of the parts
U59 = AM4378_ZDN_GPEVM
C7 C9 C64 C101 C108 C115 C127 C253 C334 C341 C372 C375 C384 C386 C387 C400 C401 C403 C404 C408 C409 = 1C_0.1uFCapacitor16V10%0402
C4 C10 C11 C16 C26 C29-C32 C42 C51-C53 C116 C222-C224 C235 C236 C240 C243 C255 C257 C259 C260 C280 C281 C283 C284 C295 C297 C300 C306 C308 C316 C317 C320 C366 C369-C371 C374 C377-C379 C410 C423 C427-C429 = 1C_0.01uFCapacitor16V10%0402
C230 C261 C273 C291 C338 C376 C383 C388 C391 C405 C424 = 1C_10uFCapacitor16V10%0805
J4 J9 J37 = 2C_Conn_DSUB9M_TH
R8-R26 R30 R38 R42 R45 R46 R49 R50 R64 R153 R158 R172 R182-R184 R186 R188 R199-R201 R203 R207 R211 R213 R221 R224 R227 R228 R273-R282 R290 R324 R325 R331 R332 R338 R341 R347 R349 R352 R356 R358 R398 R400 R405 R406 R426 R428 R435 R442 R443 R458 R459 = 1R_ZeroOhmResistor1_16W0402
U19 = 1A_MAX3232E
C237 C242 C380 C382 C407 C414 C416 C417 = 1C_0.1uFCapacitor50V10%0402
C248 C251 = 1C_47uFCapacitor16V20%1206
FB12 FB18 FB20 = 1L_FerBead_180ohm200mA
J14 J16 = 2C_Conn_3.5mm_SJ3524SMT
R174 R408 = 1R_ZeroOhmResistor1_16W0603
R4 R6 R31 R57 R99 R185 R187 R198 R210 R214 R225 R232 R289 R299 R372-R380 R396 R397 R407 R409-R418 R471 R491 = 1R_10KOhmResistor1_16W0402
U24 = 1A_SN74LVC1G125
U7 U37 U67 = 1A_SN74AVC4T245
U68 = 1A_TLV320AIC3106
Y5 = 1Y_Oscillator_12MHz_3_3V
A1 = 4P_LCD_WVGA_7in_wCapTouchOSD
C241 C396 C399 C406 C411 = 1C_1uFCapacitor10V10%0402
C249 = 1C_6.8pFCapacitor50V10%SMD0402
C250 C252 C412 = 1C_22uFCapacitor16V10%0805
C258 C335 C342 = 1C_0.001uFCapacitor50V5%0402
C265 = 1C_2200pFCapacitor50V10%SMD0402
C266-C269 C274 = 1C_0.22uFCapacitor50V10%0603
C381 = 1C_4.7uFCapacitor50V20%0805
C35 C225 C298 C309 C389 C395 = 1C_4.7uFCapacitor16V10%0603
C390 = 47nFCapacitor16V10%0402
D5 = 1E_Diode1A20V_Schottky
D6 = Diode200mA30V_Schottky
J15 = 2C_Conn_FPC_0.5mmpitch_50posbot
J17 = 2C_Conn_FPC_527450897
L3 = 1L_4.7uHInductor20%450mAsmd
L12 = 1L_4.7uHInductor30%1.7Asmd
M19 M20 = 2M_AM43xxEVM_7inLCDMntBracket
Q3 = 1Q_MOSFET_NChan_BSS138
Q5 = 1Q_NPN_FMMT458
R192 = 1R_442Kohm1_16W1%smd0402
R193 = 1R_60.4Kohm1_16W1%smd0402
R194 R238 = 1R_499Kohm1_16W1%smd0402
R197 = 1R_357Kohm1_10W1%smd0402
R204 = 1R_49.9KOhmResistor1_16W0402
R208 = 1R_680Kohm1_16W1%smd0402
R220 = 1R_15Kohm1_16W1%smd0402
R229 = 1R_100KOhmResistor1_16W0402
R419 = 1R_2OhmResistor1_10W1%0603
R420 = 1R_10ohm1_16W5%smd0402
R421 = 1R_71.5Kohm1_10W1%smd0402
R59 R216 R218 R422 = 1R_2.2KOhmResistor1_16W0402
U26 = 1A_SN74LVC32244
U27 U29 = 1A_SN74AVC8T245
U28 = 1A_SN74LVC244A
U17 U30 U35 = 1A_SN74LVC1G04
U38 = 1A_TPS65105PWP
U42 = 1A_SN74LVC1G07
U69 = 1A_TPS61081DRC
D8 = Diode200mA250V
FB11 FB23 FB24 = 1L_FerriteBead_300ohm500mA
J19 = 2C_Conn_HDMI_TypeA
R44 R47 R58 R233 R308 R487 R488 = 1R_4.7KOhmResistor1_16W0402
R234 = 1R_10KOhmResistor1_10W1%0402
R240 = 1R_51Kohm1_16W1%smd0402
R447 = 1R_4.3KOhmResistor1_16W0402
TP17 TP24 = 2H_TestPointThroughHole
U40 = 1A_SIL9022A
U43 = 1A_TPD12S016
U72 = TPS71712
U73 = 1A_SN74LVC1G08DCKT_SC70
J3 = 2H_Header12x2
PCB2 = 4P_CameraBoardAssembledPCB
J22 = 2H_Header10x2
C229 = 1C_150uFCapacitor10V10%2917
J13 = 2C_Connector_USB_A
J36 = 2H_Header_2x1
L2 = 1M_ACM2012
R116 = 1R_1KOhmResistor1_16W0402
U64 = 1A_TPD4S012
U66 = 1A_TPS2051BD
C38 C264 C278 C385 = 1C_3.3uFCapacitor16V10%0603
C238 C239 C322 C323 = 1C_100pFCapacitor16V10%0402
R28 R202 = 1R_120ohm1_16W1%smd0402
R177 R178 R295 R296 = 1R_33ohmResistor1_16W5%0402
U2 U36 = 1A_PSM712
U9 U70 = 1A_IsoReg5V_R1Z-3.305HP
U10 U31 = 1A_ISO1050
C337 = 1C_1uFCapacitor50V10%0603
J8 = 2H_Header10x2_ARMJTAG
R29 = 1R_100ohm1_16W1%SMD0402
R161-R169 R386-R395 = 1R_56KOhmResistor1_16W1%0402
SW11 SW12 = 2W_SwitchDIP5pos_smd
TP1 TP2 = 2H_Testpoint_SMD1mmCircle
U52 = 1A_CAT24C256W
C19 C25 = 1C_18pFCapacitor16V10%0402
C287 = 1C_2.2uF16V10%SMD0805
D17 = 1F_LED_Green
FB13-FB15 = 1L_FerriteBead_220ohm2A
J21 = 2C_MicroUSBAB
R48 = 1R_9.1KohmResistor1_16W1%0402
R268 = 1R_49.9OhmResistor1_16W0402
R291 = 1R_12Kohm1_16W1%SMD0402
U3 = 1A_FT2232_2
U6 U11 = 1A_SN74AVC2T244
U12 = 1A_SN74LVC2G07
U13 = 1A_SN74LVC1G00DCK
U14 = 1A_93C56EEPROM2Kbit
U44 = 1A_TPD2E001DRL
U46 = 1A_TPS79333
Y1 = 1Y_Crystal12MHzABM3

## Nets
AGND_AUD: C380.2 C382.2 C383.2 C384.2 C386.2 C387.2 C388.2 C391.2 J14.1(P1) J16.1(P1) R408.2(P2) U68.15(AVSS_ADC) U68.20(DRVSS) U68.21(DRVSS) U68.26(AVSS_DAC) U68.TPAD
AVDD10_FB: C249.2 R192.1(P1) R193.1 U38.1(FB1)
AVDD10_IND: D5.2(ANODE) L3.2 U38.5(SW1) U38.6(SW2)
DGND: C4.2 C7.2 C10.2 C11.2 C16.2 C19.2 C25.2 C26.2 C29.2 C30.2 C31.2 C32.2 C35.2 C38.2 C42.2 C51.2 C52.1 C53.1 C64.2 C101.2 C116.2 C127.2 C222.2 C223.2 C224.2 C225.2 C229.2(NEG) C230.2 C235.2 C236.2 C238.2 C239.2 C240.2 C241.2 C243.2 C250.2 C252.2 C255.2 C257.2 C258.2 C259.2 C260.2 C261.2 C266.2 C269.2 C273.2 C274.2 C280.2 C281.2 C283.2 C284.2 C287.2 C291.2 C295.2 C297.2 C298.1 C300.1 C306.2 C308.1 C309.1 C316.2 C317.1 C320.2 C322.2 C323.2 C337.2 C338.2 C366.2 C369.2 C370.2 C371.2 C372.2 C374.2 C375.2 C376.2 C377.2 C378.2 C379.2 C381.2 C385.2 C389.2 C390.2 C395.2 C396.2 C399.2 C400.2 C401.2 C403.2 C404.2 C405.2 C406.2 C407.2 C408.2 C409.2 C410.2 C411.2 C412.2 C414.2 C416.2 C417.2 C423.2 C424.2 C427.2 C428.2 C429.2 D6.2(CATHODE) FB12.2 FB18.1 J3.11 J3.12 J3.21 J8.4(GND) J8.6(GND) J8.10(GND) J8.12(GND) J8.14(GND) J8.16(GND) J8.18(GND) J8.20(GND) J9.5 J9.10 J9.11 J13.4(GND) J15.5 J15.36 J15.38 J15.48 J15.MNT1 J15.MNT2 J17.7 J17.MNT1 J17.MNT2 J19.2(DAT2_S) J19.5(DAT1_S) J19.8(DAT0_S) J19.11(CLK_S) J19.17(DDC/CEC_GND) J19.MTG1 J19.MTG2 J19.MTG3 J19.MTG4 J21.5(GND) Q3.S(SOURCE) R4.1(P1) R18.1(P1) R48.1(P1) R158.1(P1) R172.1(P1) R182.2(P2) R184.2(P2) R193.2 R197.2 R204.1(P1) R220.2(P2) R234.1 R291.2(P2) R308.1(P1) R372.1(P1) R373.1(P1) R374.1(P1) R375.1(P1) R376.1(P1) R377.1(P1) R378.1(P1) R379.1(P1) R380.1(P1) R397.2(P2) R407.1(P1) R408.1(P1) R409.1(P1) R410.1(P1) R411.1(P1) R412.1(P1) R413.1(P1) R414.1(P1) R415.1(P1) R416.1(P1) R417.1(P1) R418.1(P1) R419.1 R421.1(P1) R422.1(P1) R426.1(P1) R435.1(P1) R447.1(P1) R471.1(P1) R491.1(P1) U3.1(GND.1) U3.5(GND.2) U3.10(AGND) U3.11(GND.3) U3.13(TEST) U3.15(GND.4) U3.25(GND.5) U3.35(GND.6) U3.47(GND.7) U3.51(GND.8) U6.5(GND) U7.8(GND) U7.9(GND) U9.1(VIN-) U10.4(GND1) U11.5(GND) U12.2(GND) U12.3(2A) U13.3(GND) U14.5(VSS) U14.7(NC1) U17.3(GND) U19.15(GND) U24.3(GND) U26.B3(GND1) U26.B4(GND16) U26.D3(GND2) U26.D4(GND15) U26.E3(GND3) U26.E4(GND14) U26.G3(GND4) U26.G4(GND13) U26.K3(GND5) U26.K4(GND12) U26.M3(GND6) U26.M4(GND11) U26.N3(GND7) U26.N4(GND10) U26.R3(GND8) U26.R4(GND9) U27.2(DIR) U27.11(GND) U27.12(GND) U27.13(GND) U28.E1(GND) U29.2(DIR) U29.11(GND) U29.12(GND) U29.13(GND) U30.3(GND) U31.4(GND1) U35.3(GND) U37.8(GND) U37.9(GND) U38.7(PGND) U38.8(PGND) U38.15(C2-/MODE) U38.19(GND) U38.TP(THERM_GND) U40.43(CGND) U40.55(RSVDL) U40.57(IOGND) U40.63(AGND) U40.70(VDDQ) U40.EPAD U42.3(GND) U43.6(GND) U43.14(GND) U43.19(GND) U44.4(GND) U46.2(GND) U52.1(A0) U52.2(A1) U52.3(A2) U52.4(VSS) U64.4(GND) U66.1(GND) U67.2(1DIR) U67.8(GND) U67.9(GND) U68.42(DVSS) U68.43(SELECT) U69.4(GND) U69.8(PGND) U69.PAD(TPAD) U70.1(VIN-) U72.2(GND) U73.3(GND) Y5.2(GND) ; also on sheet 12 14 15 16 17 18 19 20 21 22 23 24 25 26 27
GND_CAN0: C9.2 C278.2 J4.3 J4.5 J4.6 J4.10 J4.11 U2.3 U9.4(VOUT-) U9.5(VOUT-) U10.5(GND2)
GND_CAN1: C253.2 C264.2 J37.3 J37.5 J37.6 J37.10 J37.11 U31.5(GND2) U36.3 U70.4(VOUT-) U70.5(VOUT-)
GNDA_ADC: J22.11 J22.12 R325.2(P2) R331.2(P2) ; also on sheet 17
GNDUSB1: FB18.2 J13.S1 J13.S2
GNDUSBJ: FB12.1 J21.S1 J21.S2 J21.S3 J21.S4
V1_2D: C405.1 C411.1 C412.1 FB23.2 FB24.2 U72.5(OUT)
V1_2D_EN: R443.1(P1) U72.3(EN)
V1_8D: C222.1 C224.1 C375.1 C376.1 J22.1 U27.23(VCCB) U27.24(VCCB) U29.23(VCCB) U29.24(VCCB) U68.36(DVDD) ; also on sheet 12 17 18 23 25
V1_8FTDI: C10.1 C30.1 C35.1 C297.1 U3.12(VCORE.1) U3.37(VCORE.2) U3.49(VREGOUT) U3.64(VCORE.3)
V3_3AUD: C383.1 C384.1 C386.1 C387.1 C388.1 C391.1 FB20.2 U68.16(DRVDD) U68.17(DRVDD) U68.24(DRVDD) U68.25(AVDD_DAC)
V3_3D: C26.1 C29.1 C32.1 C38.1 C42.1 C51.1 C52.2 C53.2 C116.1 C223.1 C230.1 C235.1 C236.1 C240.1 C243.1 C255.1 C257.1 C259.1 C260.1 C320.1 C338.1 C369.1 C370.1 C371.1 C372.1 C374.1 C377.1 C378.1 C379.1 C385.1 C410.1 C423.1 C424.1 C428.1 D8.2(Anode) FB11.2 FB20.1 J8.1(VTREF) J8.2(VSPLY) J17.8 R6.2(P2) R31.2(P2) R44.2(P2) R58.2(P2) R99.2(P2) R161.2(P2) R162.2(P2) R163.2(P2) R164.2(P2) R165.2(P2) R166.2(P2) R167.2(P2) R168.2(P2) R169.2(P2) R187.2(P2) R198.2(P2) R216.2(P2) R218.2(P2) R225.2(P2) R232.2(P2) R233.2(P2) R299.2(P2) R386.2(P2) R387.2(P2) R388.2(P2) R389.2(P2) R390.2(P2) R391.2(P2) R392.2(P2) R393.2(P2) R394.2(P2) R395.2(P2) R396.1(P1) R406.2(P2) R407.2(P2) R443.2(P2) R459.2(P2) U6.8(VCCB) U7.16(VCCB) U9.2(VIN+) U10.1(VCC1) U11.1(VCCA) U11.3(A2) U12.5(VCC) U13.5(VCC) U17.5(VCC) U19.16(VCC) U24.5(VCC) U26.C3(VCC) U26.C4(VCC) U26.F3(VCC) U26.F4(VCC) U26.L3(VCC) U26.L4(VCC) U26.P3(VCC) U26.P4(VCC) U27.1(VCCA) U28.A3(VCC) U29.1(VCCA) U30.5(VCC) U31.1(VCC1) U35.5(VCC) U37.1(VCCA) U37.2(1DIR) U37.3(2DIR) U37.16(VCCB) U42.5(VCC) U43.24(VCCA) U52.8(VCC) U67.1(VCCA) U67.3(2DIR) U67.16(VCCB) U68.44(IOVDD) U68.45(MFP0) U68.46(MFP1) U70.2(VIN+) U73.5(VCC) Y5.4(VCC) ; also on sheet 12 14 15 16 17 18 20 21 22 23 24 25 27
V3_3FTDI: C11.1 C16.1 C31.1 C64.1 C283.1 C284.1 C287.1 C306.1 C316.1 C317.2 D17.2(Anode) FB14.2 FB15.2 R57.2(P2) R289.2(P2) U3.20(VCCIO.1) U3.31(VCCIO.2) U3.42(VCCIO.3) U3.50(VREGIN) U3.56(VCCIO.4) U6.1(VCCA) U7.1(VCCA) U7.2(1DIR) U7.3(2DIR) U11.8(VCCB) U14.6(NC2) U14.8(VCC) U46.5(OUT)
V5_0D: C427.1 R487.2(P2) R488.2(P2) U43.11(VCC5V) U66.2(IN) U66.3(IN) ; also on sheet 16 23
V5_0HDMICONN: C429.1 J19.18(+5V) U43.13(5V_OUT)
VBAT: C4.1 C252.1 C291.1 C389.1 C399.1 C406.1 J3.1 J22.2 L3.1 Q5.1(C) R210.2(P2) R214.1(P1) R405.2(P2) U38.4(VIN) U46.1(IN) U69.2(VIN) U72.1(IN) ; also on sheet 12 18 19 21 23 27
VBUS1_OTG_CAP: C229.1(POS) J36.2 R174.2(P2)
VDDA_ADC: R332.1(P1) ; also on sheet 17
VDDA_MC_ADC: R324.1(P1) ; also on sheet 17
VDDLCD_BASE: Q5.3(B) U38.3(BASE)
AM437X_AIN0: J22.3 U59.AA12(ADC0_AIN0)
AM437X_AIN1: J22.5 U59.Y12(ADC0_AIN1)
AM437X_AIN2: J22.7 U59.Y13(ADC0_AIN2)
AM437X_AIN3: J22.9 U59.AA13(ADC0_AIN3)
AM437X_AIN4: J22.4 U59.AB13(ADC0_AIN4)
AM437X_AIN5: J22.6 U59.AC13(ADC0_AIN5)
AM437X_AIN6: J22.8 U59.AD13(ADC0_AIN6)
AM437X_AIN7: J22.10 U59.AE13(ADC0_AIN7) ; also on sheet 23
AM437X_CAM1_DATA0: R281.2(P2) U59.AB20(CAM1_DATA0)
AM437X_CAM1_DATA1: R9.2(P2) U59.AC21(CAM1_DATA1)
AM437X_CAM1_DATA2: R11.2(P2) U59.AD21(CAM1_DATA2)
AM437X_CAM1_DATA3: R14.2(P2) U59.AE22(CAM1_DATA3)
AM437X_CAM1_DATA4: R15.2(P2) U59.AD22(CAM1_DATA4)
AM437X_CAM1_DATA5: R276.2(P2) U59.AE23(CAM1_DATA5)
AM437X_CAM1_DATA6: R280.1(P1) U59.AD23(CAM1_DATA6)
AM437X_CAM1_DATA7: R10.1(P1) U59.AE24(CAM1_DATA7)
AM437X_CAM1_DATA8: R12.1(P1) U59.AD24(CAM1_DATA8)
AM437X_CAM1_DATA9: R279.1(P1) U59.AC24(CAM1_DATA9)
AM437X_CAM1_HSYNC: R8.1(P1) U59.AD25(CAM1_HSYNC)
AM437X_CAM1_PCLK: R13.2(P2) U59.AE21(CAM1_PCLK)
AM437X_CAM1_VSYNC: R282.1(P1) U59.AC23(CAM1_VSYNC)
AM437X_CLKOUT1: R358.2(P2) U59.D24(XDMA_EVENT_INTR0/CLKOUT1)
AM437X_DCAN0_RX: C323.1 R296.1 U59.L22(UART1_RTSN/DCAN0_RX)
AM437X_DCAN0_TX: R295.1 U59.K22(UART1_CTSN/DCAN0_TX)
AM437X_DCAN1_RX: C239.1 R178.1 U59.L21(UART1_TXD/DCAN1_RX)
AM437X_DCAN1_TX: R177.1 U59.K21(UART1_RXD/DCAN1_TX)
AM437X_HDMI_INTn: R228.2(P2) ; also on sheet 21
AM437X_LCD_AC_BIAS_EN: R168.1(P1) R373.2(P2) U28.B2(2A4) U28.D1(1A4) U59.A24(DSS_AC_BIAS_EN)
AM437X_LCD_DATA0: R391.1(P1) SW12.10 U26.A5(1A1) U26.J5(5A1) U59.B22(DSS_DATA0)
AM437X_LCD_DATA1: R392.1(P1) SW12.9 U26.A6(1A2) U26.J6(5A2) U59.A21(DSS_DATA1)
AM437X_LCD_DATA2: R393.1(P1) SW12.8 U26.B5(1A3) U26.K5(5A3) U59.B21(DSS_DATA2)
AM437X_LCD_DATA3: R394.1(P1) SW12.7 U26.B6(1A4) U26.K6(5A4) U59.C21(DSS_DATA3)
AM437X_LCD_DATA4: R395.1(P1) SW12.6 U26.C5(2A1) U26.L5(6A1) U59.A20(DSS_DATA4)
AM437X_LCD_DATA5: R386.1(P1) SW11.10 U26.C6(2A2) U26.L6(6A2) U59.B20(DSS_DATA5)
AM437X_LCD_DATA6: R387.1(P1) SW11.9 U26.D5(2A3) U26.M5(6A3) U59.C20(DSS_DATA6)
AM437X_LCD_DATA7: R163.1(P1) R378.2(P2) U26.D6(2A4) U26.M6(6A4) U59.E19(DSS_DATA7)
AM437X_LCD_DATA8: R166.1(P1) R375.2(P2) U26.E5(3A1) U26.N5(7A1) U59.A19(DSS_DATA8)
AM437X_LCD_DATA9: R388.1(P1) SW11.8 U26.E6(3A2) U26.N6(7A2) U59.B19(DSS_DATA9)
AM437X_LCD_DATA10: R164.1(P1) R377.2(P2) U26.F5(3A3) U26.P5(7A3) U59.A18(DSS_DATA10)
AM437X_LCD_DATA11: R165.1(P1) R376.2(P2) U26.F6(3A4) U26.P6(7A4) U59.B18(DSS_DATA11)
AM437X_LCD_DATA12: R389.1(P1) SW11.7 U26.G5(4A1) U26.R5(8A1) U59.C19(DSS_DATA12)
AM437X_LCD_DATA13: R390.1(P1) SW11.6 U26.G6(4A2) U26.R6(8A2) U59.D19(DSS_DATA13)
AM437X_LCD_DATA14: R162.1(P1) R379.2(P2) U26.H5(4A3) U26.T5(8A3) U59.C17(DSS_DATA14)
AM437X_LCD_DATA15: R161.1(P1) R380.2(P2) U26.H6(4A4) U26.T6(8A4) U59.D17(DSS_DATA15)
AM437X_LCD_DATA16: U27.21(B1) U29.21(B1) U59.A11(GPMC_AD15/DSS_DATA16)
AM437X_LCD_DATA17: U27.20(B2) U29.20(B2) U59.B11(GPMC_AD14/DSS_DATA17)
AM437X_LCD_DATA18: U27.19(B3) U29.19(B3) U59.C11(GPMC_AD13/DSS_DATA18)
AM437X_LCD_DATA19: U27.18(B4) U29.18(B4) U59.E11(GPMC_AD12/DSS_DATA19)
AM437X_LCD_DATA20: U27.17(B5) U29.17(B5) U59.D11(GPMC_AD11/DSS_DATA20)
AM437X_LCD_DATA21: U27.16(B6) U29.16(B6) U59.F11(GPMC_AD10/DSS_DATA21)
AM437X_LCD_DATA22: U27.15(B7) U29.15(B7) U59.A10(GPMC_AD9/DSS_DATA22)
AM437X_LCD_DATA23: U27.14(B8) U29.14(B8) U59.B10(GPMC_AD8/DSS_DATA23)
AM437X_LCD_HSYNC: R167.1(P1) R374.2(P2) U28.B1(1A2) U28.D2(2A2) U59.A23(DSS_HSYNC)
AM437X_LCD_PCLK: U28.A1(1A1) U28.E3(2A1) U59.A22(DSS_PCLK)
AM437X_LCD_VSYNC: R169.1(P1) R372.2(P2) U28.C1(1A3) U28.C3(2A3) U59.B23(DSS_VSYNC)
AM437X_MAG_ADC0: J22.13 U59.AC16(ADC1_AIN0)
AM437X_MAG_ADC1: J22.15 U59.AB16(ADC1_AIN1)
AM437X_MAG_ADC2: J22.17 U59.AA16(ADC1_AIN2)
AM437X_MAG_ADC3: J22.19 U59.AB15(ADC1_AIN3)
AM437X_MAG_ADC4: J22.14 U59.AA15(ADC1_AIN4)
AM437X_MAG_ADC5: J22.16 U59.Y15(ADC1_AIN5)
AM437X_MAG_ADC6: J22.18 U59.AE16(ADC1_AIN6)
AM437X_MAG_ADC7: J22.20 U59.AD16(ADC1_AIN7)
AM437X_MCASP1_AXR3: R491.2(P2) U24.4(Y) U59.A16(RMII1_REFCLK/MCASP1_AXR3)
AM437X_STATUS_LED1: R46.1(P1) ; also on sheet 19 21
AM437X_STATUS_LED2: R45.1(P1) ; also on sheet 19 21
AM437X_USB1_CE: TP17.1 U59.U22(USB1_CE)
AM437X_USB1_DM: L2.2 U59.V25(USB1_DM)
AM437X_USB1_DP: L2.1 U59.V24(USB1_DP)
AM437X_USB1_DRVVBUS: R356.2(P2) U59.F25(USB1_DRVVBUS)
AM437X_USB1_ID: R352.2(P2) U59.U25(USB1_ID)
AM437X_USB1_VBUS: R116.2(P2) U59.T25(USB1_VBUS)
AM437X_VREFN: C341.2 C342.2 R331.1(P1) U59.AE14(ADC0_VREFN)
AM437X_VREFP: C341.1 C342.1 R332.2(P2) U59.AD14(ADC0_VREFP)
AUD_HPLOUT: C248.1 U68.18(HPLOUT)
AUD_HPLOUT_JCK: C248.2 J16.2(P2)
AUD_HPROUT: C251.1 U68.23(HPROUT)
AUD_HPROUT_JCK: C251.2 J16.3(P3)
AUD_LINEINL: C237.1 U68.3(LINE1LP)
AUD_LINEINL_JCK: C237.2 J14.2(P2)
AUD_LINEINR: C242.1 U68.5(LINE1RP)
AUD_LINEINR_JCK: C242.2 J14.3(P3)
AUD_RESETn: R400.1(P1) U68.33(RESETn)
AUDIO_MSTRCLK: R17.2(P2) R153.1(P1) R358.1(P1) U37.7(2A2) U67.7(2A2) ; also on sheet 12
BKLT_EN: Q3.G(GATE) R187.1(P1) R188.1(P1)
BKLT_L: L12.1 U69.1(L)
BKLT_SW: L12.2 U69.10(SW)
CAM1_DATA0: J3.3 R281.1(P1)
CAM1_DATA1: J3.5 R9.1(P1)
CAM1_DATA2: J3.7 R11.1(P1)
CAM1_DATA3: J3.13 R14.1(P1)
CAM1_DATA4: J3.15 R15.1(P1)
CAM1_DATA5: J3.17 R276.1(P1)
CAM1_DATA6: J3.6 R280.2(P2)
CAM1_DATA7: J3.8 R10.2(P2)
CAM1_DATA8: J3.10 R12.2(P2)
CAM1_DATA9: J3.14 R279.2(P2)
CAM1_FIELD: J3.20 R275.2(P2)
CAM1_GIO0: J3.16 R278.2(P2)
CAM1_GIO1: J3.18 R277.2(P2)
CAM1_HSYNC: J3.4 R8.2(P2)
CAM1_PCLK: J3.9 R13.1(P1)
CAM1_SRCCLK: J3.23 R17.1(P1)
CAM1_VSYNC: J3.2 R282.2(P2)
CAM1_WEN: J3.19 R16.1(P1)
CAN0_H: J4.7 R28.2(P2) U2.1 U10.7(CANH)
CAN0_L: J4.2 R28.1(P1) U2.2 U10.6(CANL)
CAN0_RXDF: R296.2 U10.2(RXD)
CAN0_TXDF: C322.1 R295.2 U10.3(TXD)
CAN1_H: J37.7 R202.2(P2) U31.7(CANH) U36.1
CAN1_L: J37.2 R202.1(P1) U31.6(CANL) U36.2
CAN1_RXDF: R178.2 U31.2(RXD)
CAN1_TXDF: C238.1 R177.2 U31.3(TXD)
COMP: C265.2 U38.22(COMP)
COMP_CAP: C265.1 R220.1(P1)
EECS: U3.63(EECS) U14.1(CS)
EEDATA: R59.1(P1) U3.61(EEDATA) U14.3(DI)
EESK: U3.62(EESK) U14.2(CLK)
EMU_RSTn: C7.1 J8.15(nSRST) R29.1(P1) R31.1(P1)
EMU_USB_DM: J21.2(DM) U3.7(DM) U44.3(IO1)
EMU_USB_DP: J21.3(DP) U3.8(DP) U44.5(IO2)
F_ADBUS0: R30.2(P2) U3.16(ADBUS0)
F_ADBUS1: R26.2(P2) U3.17(ADBUS1)
F_ADBUS2: R25.2(P2) U3.18(ADBUS2)
F_ADBUS3: R24.2(P2) U3.19(ADBUS3)
F_ADBUS4: R23.2(P2) U3.21(ADBUS4)
F_ADBUS5: R21.2(P2) U3.26(ACBUS0)
F_ADBUS6: R22.2(P2) U3.23(ADBUS6)
F_ADBUS7: R19.2(P2) U3.30(ACBUS4)
FT_SRESET: R21.1(P1) R308.2(P2) U13.1(A)
FT_SRESETB: R64.2(P2) U12.6(1Y)
FT_SRESETn: U12.1(1A) U13.4(Y)
FT_VBUS: R49.1(P1) U13.2(B)
FTDI_REF: R291.1(P1) U3.6(REF)
FTDI_XTIN: C25.1 U3.2(XTIN) Y1.1
FTDI_XTOUT: C19.1 U3.3(XTOUT) Y1.2
GP_I2C_SCL: R201.1(P1) R227.2(P2) U68.1(SCL) ; also on sheet 12 21 23 27
GP_I2C_SDA: R200.1(P1) R224.2(P2) U68.2(SDA) ; also on sheet 12 21 23 27
HDMI_AUDBCLK: R213.1(P1) U40.45(SCK)
HDMI_AUDD0: R428.1(P1) U40.41(SD0)
HDMI_AUDFSX: R211.1(P1) U40.44(WS)
HDMI_AUDMCLK: R207.1(P1) U40.38(MCLK)
HDMI_CEC: R240.1(P1) U40.71(CEC_A) U43.1(CEC_A)
HDMI_CEC_D: R221.2(P2) U40.50(CEC_D)
HDMI_CLK+: J19.10(CLK+) U40.59(TXC+) U43.16(TMDS_CK+)
HDMI_CLK-: J19.12(CLK-) U40.58(TXC-) U43.15(TMDS_CK-)
HDMI_CT_HPD: R458.2(P2) R459.1(P1) U43.12(CT_HPD)
HDMI_D0: U26.J2(5Y1) U40.32(VDATA_IN0)
HDMI_D1: U26.J1(5Y2) U40.31(VDATA_IN1)
HDMI_D2: U26.K2(5Y3) U40.30(VDATA_IN2)
HDMI_D3: U26.K1(5Y4) U40.29(VDATA_IN3)
HDMI_D4: U26.L2(6Y1) U40.28(VDATA_IN4)
HDMI_D5: U26.L1(6Y2) U40.27(VDATA_IN5)
HDMI_D6: U26.M2(6Y3) U40.25(VDATA_IN6)
HDMI_D7: U26.M1(6Y4) U40.24(VDATA_IN7)
HDMI_D8: U26.N2(7Y1) U40.23(VDATA_IN8)
HDMI_D9: U26.N1(7Y2) U40.20(VDATA_IN9)
HDMI_D10: U26.P2(7Y3) U40.19(VDATA_IN10)
HDMI_D11: U26.P1(7Y4) U40.18(VDATA_IN11)
HDMI_D12: U26.R2(8Y1) U40.17(VDATA_IN12)
HDMI_D13: U26.R1(8Y2) U40.16(VDATA_IN13)
HDMI_D14: U26.T2(8Y3) U40.15(VDATA_IN14)
HDMI_D15: U26.T1(8Y4) U40.14(VDATA_IN15)
HDMI_D16: U27.3(A1) U40.13(VDATA_IN16)
HDMI_D17: U27.4(A2) U40.11(VDATA_IN17)
HDMI_D18: U27.5(A3) U40.10(VDATA_IN18)
HDMI_D19: U27.6(A4) U40.9(VDATA_IN19)
HDMI_D20: U27.7(A5) U40.8(VDATA_IN20)
HDMI_D21: U27.8(A6) U40.7(VDATA_IN21)
HDMI_D22: U27.9(A7) U40.6(VDATA_IN22)
HDMI_D23: U27.10(A8) U40.4(VDATA_IN23)
HDMI_DE: U28.B3(2Y4) U40.33(DE)
HDMI_EXTSWING: R447.2(P2) U40.56(EXT_SWING)
HDMI_HPLG: R234.2 U40.54(HPD) U43.4(HPD_A)
HDMI_HSYNC: U28.D3(2Y2) U40.34(HSYNC)
HDMI_I2C_SCL: R227.1(P1) U40.1(CSCL)
HDMI_I2C_SDA: R224.1(P1) U40.2(CSDA)
HDMI_I2CSCL: R218.1(P1) U40.49(DSCL) U43.2(SCL_A)
HDMI_I2CSDA: R216.1(P1) U40.48(DSDA) U43.3(SDA_A)
HDMI_INTn: R225.1(P1) R228.1(P1) U40.52(INT)
HDMI_LSOE: R458.1(P1) U43.5(LS_OE)
HDMI_PCLK: U28.E2(2Y1) U40.22(IDCK)
HDMI_TX0+: J19.7(DAT0+) U40.62(TX0+) U43.18(TMDS_D0+)
HDMI_TX0-: J19.9(DAT0-) U40.61(TX0-) U43.17(TMDS_D0-)
HDMI_TX1+: J19.4(DAT1+) U40.65(TX1+) U43.21(TMDS_D1+)
HDMI_TX1-: J19.6(DAT1-) U40.64(TX1-) U43.20(TMDS_D1-)
HDMI_TX2+: J19.1(DAT2+) U40.68(TX2+) U43.23(TMDS_D2+)
HDMI_TX2-: J19.3(DAT2-) U40.67(TX2-) U43.22(TMDS_D2-)
HDMI_VSYNC: U28.C2(2Y3) U40.35(VSYNC)
HDMICONN_CEC: J19.13(CEC) U43.7(CEC_B)
HDMICONN_HPLG: J19.19(HPLG) R471.2(P2) U43.10(HPD_B)
HDMICONN_I2CSCL: J19.15(SCL) R487.1(P1) U43.8(SCL_B)
HDMICONN_I2CSDA: J19.16(SDA) R488.1(P1) U43.9(SDA_B)
I2C0_SCL: R274.1(P1) U52.6(SCL) ; also on sheet 23
I2C0_SDA: R273.1(P1) U52.5(SDA) ; also on sheet 23
JTAG_DBGACK: J8.19(DBGACK) TP2.1
JTAG_DBGRQ: J8.17(DBGRQ) TP1.1
JTAG_TCK: R38.2(P2) R42.2(P2) U7.13(1B1) U59.AA25(JTAG_TCK)
JTAG_TDI: J8.5(TDI) U7.12(1B2) U59.Y20(JTAG_TDI)
JTAG_TDO: J8.13(TDO) U11.2(A1) U59.AA24(JTAG_TDO)
JTAG_TMS: J8.7(TMS) R44.1(P1) U7.11(2B1) U59.Y24(JTAG_TMS)
JTAG_TRSTn: J8.3(nTRST) R58.1(P1) U7.10(2B2) U59.Y25(JTAG_TRSTn)
JTAGPOD_PRES: R50.1(P1) U17.4(Y)
LCD_AVDD_EN: R210.1(P1) U38.24(EN)
LCD_BACKLIGHT: R188.2(P2) U59.G24(ECAP0_IN_PWM0_OUT)
LCD_BLUE0: J15.19 U26.A2(1Y1)
LCD_BLUE1: J15.18 U26.A1(1Y2)
LCD_BLUE2: J15.17 U26.B2(1Y3)
LCD_BLUE3: J15.16 U26.B1(1Y4)
LCD_BLUE4: J15.15 U26.C2(2Y1)
LCD_BLUE5: J15.14 U26.C1(2Y2)
LCD_BLUE6: J15.13 U26.D2(2Y3)
LCD_BLUE7: J15.12 U26.D1(2Y4)
LCD_DITHER: J15.47 R186.1(P1)
LCD_EN: J15.9 U28.E4(1Y4)
LCD_GREEN0: J15.27 U26.E2(3Y1)
LCD_GREEN1: J15.26 U26.E1(3Y2)
LCD_GREEN2: J15.25 U26.F2(3Y3)
LCD_GREEN3: J15.24 U26.F1(3Y4)
LCD_GREEN4: J15.23 U26.G2(4Y1)
LCD_GREEN5: J15.22 U26.G1(4Y2)
LCD_GREEN6: J15.21 U26.H2(4Y3)
LCD_GREEN7: J15.20 U26.H1(4Y4)
LCD_HSYNC: J15.11 U28.C4(1Y2)
LCD_LEFTRIGHT: J15.39 R183.1(P1)
LCD_PCLK: J15.37 U28.B4(1Y1)
LCD_RED0: J15.35 U29.3(A1)
LCD_RED1: J15.34 U29.4(A2)
LCD_RED2: J15.33 U29.5(A3)
LCD_RED3: J15.32 U29.6(A4)
LCD_RED4: J15.31 U29.7(A5)
LCD_RED5: J15.30 U29.8(A6)
LCD_RED6: J15.29 U29.9(A7)
LCD_RED7: J15.28 U29.10(A8)
LCD_RESETn: C241.1 J15.44 R185.1(P1)
LCD_UPDOWN: J15.40 R184.1(P1)
LCD_VSYNC: J15.10 U28.D4(1Y3)
LOWPOWERn: U73.1(A) ; also on sheet 21
LOWPWR_RSTn: R400.2(P2) R442.2(P2) U73.4(Y)
MCASP1_ACLKX: U37.4(1A1) U59.B14(GMII1_CRS/MCASP1_ACLKX) U67.4(1A1)
MCASP1_AXR2: U37.6(2A1) U59.D16(GMII1_COL/MCASP1_AXR2) U67.6(2A1)
MCASP1_FSX: U37.5(1A2) U59.B13(GMII1_RXERR/MCASP1_FSX) U67.5(1A2)
RS232_0CTS: J9.8 U19.8(RIN2)
RS232_0RTS: J9.7 U19.7(DOUT2)
RS232_0RXD: J9.2 U19.13(RIN1)
RS232_0TXD: J9.3 U19.14(DOUT1)
RTCK: J8.11(RTCK) R38.1(P1)
SEL_LCDn: R398.1(P1) U26.A3(1~{OE}) U26.A4(2~{OE}) U26.H3(4~{OE}) U26.H4(3~{OE}) U28.A2(1OE#) U29.22(~{OE}) U30.4(Y)
SEL_LCDORHDMIn: R203.1(P1) R232.1(P1) U26.J3(5~{OE}) U26.J4(6~{OE}) U26.T3(8~{OE}) U26.T4(7~{OE}) U27.22(~{OE}) U28.A4(2OE#) U30.2(A) U42.2(A) ; also on sheet 21
SYS_RESETn: R29.2(P2) R64.1(P1) U35.2(A) U73.2(B) ; also on sheet 14 24
TCK: J8.9(TCK) R42.1(P1)
TOUCH_INTn: R199.1(P1) ; also on sheet 21
TSC_RESETn: J17.6 R422.2(P2) U35.4(Y)
UART0_CTSn: R338.1(P1) U19.9(ROUT2)
UART0_RTSn: R341.1(P1) U19.10(DIN2)
UART0_RXD: R349.1(P1) U19.12(ROUT1)
UART0_TXD: R347.1(P1) U19.11(DIN1)
USB1_CONN_DM: J13.2(DM) L2.3 U64.2(D-)
USB1_CONN_DP: J13.3(DP) L2.4 U64.1(D+)
USB1_ID: R172.2(P2) R352.1(P1) U64.3(ID)
USB1_OVRCURn: R396.2(P2) U66.5(~{OC})
USB1_VBUS_EN: R356.1(P1) R397.1(P1) U66.4(EN)
USBJTAG_ENn: R50.2(P2) U6.4(~{OE}) U7.14(2~{OE}) U7.15(1~{OE}) U11.4(~{OE})
VCAN0: C9.1 C278.1 J4.9 U9.7(VOUT+) U10.8(VCC2)
VCAN1: C253.1 C264.1 J37.9 U31.8(VCC2) U70.7(VOUT+)
VCOMC+: C267.2 U38.16(C1+)
VCOMC-: C267.1 U38.17(C1-)
VCOMIN: C258.1 R194.1(P1) R197.1 U38.11(VCOMIN)
VFTDI_PHY: C308.2 C309.2 FB15.1 U3.4(VPHY)
VFTDI_PLL: C298.2 C300.2 FB14.1 U3.9(VPLL)
VGHFB: R204.2(P2) R208.1(P1) U38.12(FB3)
VGL_DRV: C268.2 U38.18(DRV)
VGL_FB: R229.2(P2) R238.1(P1) U38.21(FB2)
VGL_REF: C269.1 R229.1(P1) U38.20(REF)
VHDMI_AVCC12: C261.1 C416.1 C417.1 FB23.1 U40.60(AVCC12) U40.66(AVCC12)
VHDMI_CVCC12: C400.1 C401.1 C403.1 C404.1 C408.1 C409.1 FB24.1 U40.5(CVCC12) U40.12(CVCC12) U40.26(CVCC12) U40.42(CVCC12) U40.47(CVCC12) U40.53(CVCC12)
VHDMI_IOVCC: C273.1 C407.1 C414.1 FB11.1 U40.3(IOVCC) U40.21(IOVCC) U40.46(IOVCC)
VLCD_AVDD: C249.1 C250.1 D5.1(CATHODE) J15.43 R192.2(P2) R194.2(P2) U38.9(SUPP)
VLCD_DVDD: C395.1 J15.7 Q5.2(E) R183.2(P2) R185.2(P2) R186.2(P2) U38.2(FB4)
VLCD_VCOM: C396.1 J15.6 J15.46 U38.10(VCOM)
VLCD_VGH: C266.1 J15.41 R208.2(P2) U38.13(OUT3)
VLCD_VGL: C274.1 D6.1(ANODE) J15.42 R238.2(P2)
VLED+: C381.1 J15.1 J15.2 U69.9(OUT)
VLED-: J15.3 J15.4 R419.2 U69.5(FB)
VUSB_FTDI: C281.1 FB13.2 R47.2(P2) R290.1(P1)
VUSB_JTAG: C280.1 FB13.1 J21.1(VBUS) U44.1(VCC)
VUSB_VBUS1: C225.1 C366.1 J13.1(VBUS) J36.1 R116.1(P1) R174.1(P1) U64.6(VBUS) U66.6(OUT) U66.7(OUT) U66.8(OUT)
N10547354: R406.1(P1) U69.6(EN)
N10547358: C390.1 R420.2(P2) R421.2(P2) U69.3(SS)
N10547410: Q3.D(DRAIN) R420.1(P1)
N10547584: R405.1(P1) U69.7(FSW)
N10899547: R214.2(P2) U38.23(ENR) U42.4(Y)
N10900827: C268.1 D6.3(CATHANOD)
N10937487: C101.1 U19.6(V-)
N10937491: C127.1 U19.2(V+)
N10937507: C115.2 U19.3(C1-)
N10937511: C108.1 U19.4(C2+)
N10937515: C108.2 U19.5(C2-)
N10937529: C115.1 U19.1(C1+)
N10937893: R347.2(P2) U59.J24(UART0_TXD)
N10937905: R341.2(P2) U59.J25(UART0_RTSn)
N10937909: R349.2(P2) U59.K25(UART0_RXD)
N10937921: R338.2(P2) U59.L25(UART0_CTSn)
N12433526: R442.1(P1) U40.51(RESETn)
N12433674: R233.1(P1) U40.72(CI2CA)
N12433889: R426.2(P2) U40.36(SPDIF)
N12434699: R435.2(P2) U40.69(IO_SEL)
N12434935: D8.1(Cathode) R240.2(P2)
N12435159: R221.1(P1) TP24.1
N12957779: R20.2(P2) U3.28(ACBUS2)
N12957783: R4.2(P2) R20.1(P1) U11.6(B2)
N12957791: R18.2(P2) U3.32(ACBUS5)
N12957851: R47.1(P1) R48.2(P2) R49.2(P2) U3.59(BCBUS7)
N12958009: R289.1(P1) U3.14(RESET#)
N12958129: D17.1(Cathode) R268.1(P1)
N12958219: R57.1(P1) R59.2(P2) U14.4(DO)
N12958347: R268.2(P2) U3.60(PWREN#)
N12958943: R25.1(P1) U11.7(B1)
N12959041: R290.2(P2) U46.3(EN)
N12959089: C295.1 U46.4(NR)
N15198290: C382.1 U68.6(LINE1RM)
N15198329: C380.1 U68.4(LINE1LM)
N15592722: J3.22 R274.2(P2)
N15592726: J3.24 R273.2(P2)
N16423861: R6.1(P1) R278.1(P1)
N17034041: R409.2(P2) SW12.1
N17034069: R410.2(P2) SW12.2
N17034107: R411.2(P2) SW12.3
N17034117: R412.2(P2) SW12.4
N17034161: R413.2(P2) SW12.5
N17104819: R158.2(P2) Y5.1(OE)
N17208812: J15.8 R182.1(P1)
N17283795: C334.2 C335.2 R325.1(P1) U59.AD15(ADC1_VREFN)
N17283801: C334.1 C335.1 R324.2(P2) U59.AE15(ADC1_VREFP)
N17345501: R414.2(P2) SW11.1
N17345515: R415.2(P2) SW11.2
N17345519: R416.2(P2) SW11.3
N17345529: R417.2(P2) SW11.4
N17345551: R418.2(P2) SW11.5
N17511082: R22.1(P1) U6.2(A1)
N17511110: R19.1(P1) U6.3(A2)
N17512123: R30.1(P1) U7.4(1A1)
N17512125: R26.1(P1) U7.5(1A2)
N17512127: R24.1(P1) U7.6(2A1)
N17512129: R23.1(P1) U7.7(2A2)
N17514704: C337.1 J8.8(GND) R99.1(P1) U17.2(A)
N17517305: R153.2(P2) Y5.3(CLK)
N17517963: R398.2(P2) U24.1(~{OE}) U67.14(2~{OE}) U67.15(1~{OE})
N17518729: R207.2(P2) U37.10(2B2)
N17518739: R428.2(P2) U37.11(2B1)
N17518741: R213.2(P2) U37.13(1B1)
N17518743: R211.2(P2) U37.12(1B2)
N17518767: R203.2(P2) U37.14(2~{OE}) U37.15(1~{OE})
N17546871: U67.13(1B1) U68.38(BCLK)
N17546880: U67.12(1B2) U68.39(WCLK)
N17546889: U67.10(2B2) U68.37(MCLK)
N17547178: U67.11(2B1) U68.40(DIN)
N17547363: U24.2(A) U68.41(DOUT)
N17638051: R46.2(P2) U6.7(B1)
N17638054: R45.2(P2) U6.6(B2)
N17769726: J17.5 R201.2(P2)
N17769728: J17.4 R200.2(P2)
N17769730: J17.3 R198.1(P1) R199.2(P2)
N18136628: R299.1(P1) U52.7(WP)

Not connected (* = marked no-connect by the designer): J4 1* 4* 8; J9 1* 4* 6* 9*; J14 10(P10)*; J15 45 49 50; J16 10(P10)*; J17 1 2; J19 14(NC)*; J21 4(ID)*; J37 1* 4* 8; R16 2(P2)*; R275 1(P1)*; R277 1(P1)*; U3 22(ADBUS5)* 24(ADBUS7)* 27(ACBUS1)* 29(ACBUS3)* 33(ACBUS6)* 34(ACBUS7)* 36(SUSPEND#) 38(BDBUS0)* 39(BDBUS1)* 40(BDBUS2)* 41(BDBUS3)* 43(BDBUS4)* 44(BDBUS5)* 45(BDBUS6)* 46(BDBUS7)* 48(BCBUS0)* 52(BCBUS1)* 53(BCBUS2)* 54(BCBUS3)* 55(BCBUS4)* 57(BCBUS5)* 58(BCBUS6)*; U9 10(NC); U12 4(2Y)*; U17 1(NC)*; U30 1(NC)*; U35 1(NC)*; U38 14(C2+); U40 37(SD3)* 39(SD2)* 40(SD1)*; U42 1(NC)*; U44 2(NC)*; U64 5(NC)*; U68 7(LINE2LP)* 8(LINE2LM)* 9(LINE2RP)* 10(LINE2RM)* 11(MIC3L)* 12(MICDET)* 13(MICBIAS)* 14(MIC3R)* 19(HPLCOM)* 22(HPRCOM)* 27(MONO_LOP)* 28(MONO_LOM)* 29(LEFT_LOP)* 30(LEFT_LOM)* 31(RIGHT_ROP)* 32(RIGHT_ROM)* 34(GPIO2)* 35(GPIO1)* 47(MFP2)* 48(MFP3)*; U70 10(NC); U72 4(NR)*

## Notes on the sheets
sheet 1
- USB JTAG
sheet 2
- Audio
  Headphone Out
- Audio
  Line in
sheet 4
- BackLight Power
sheet 7
- UART #0 RS-232
sheet 9
- USB1 Port
sheet 10
- ID Memory
- JTAG Connector
- Boot Configuration
